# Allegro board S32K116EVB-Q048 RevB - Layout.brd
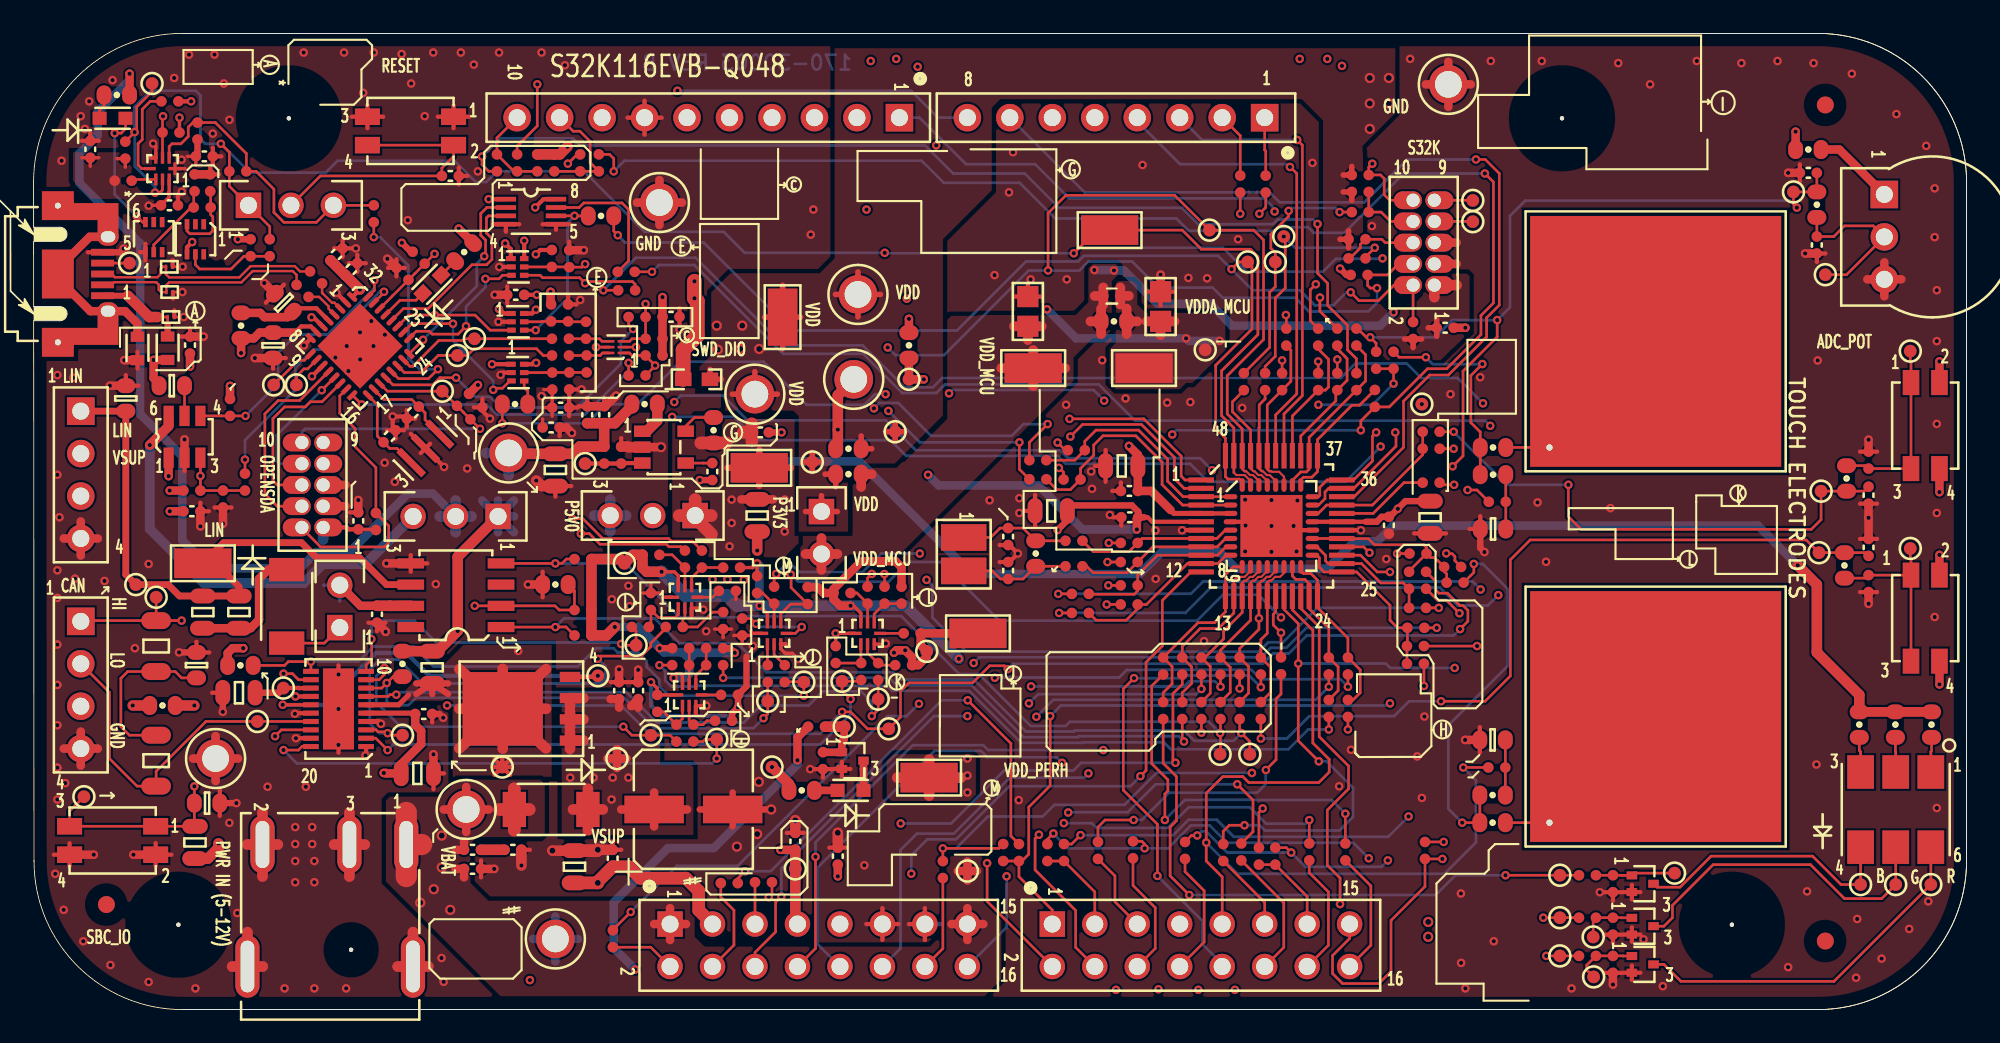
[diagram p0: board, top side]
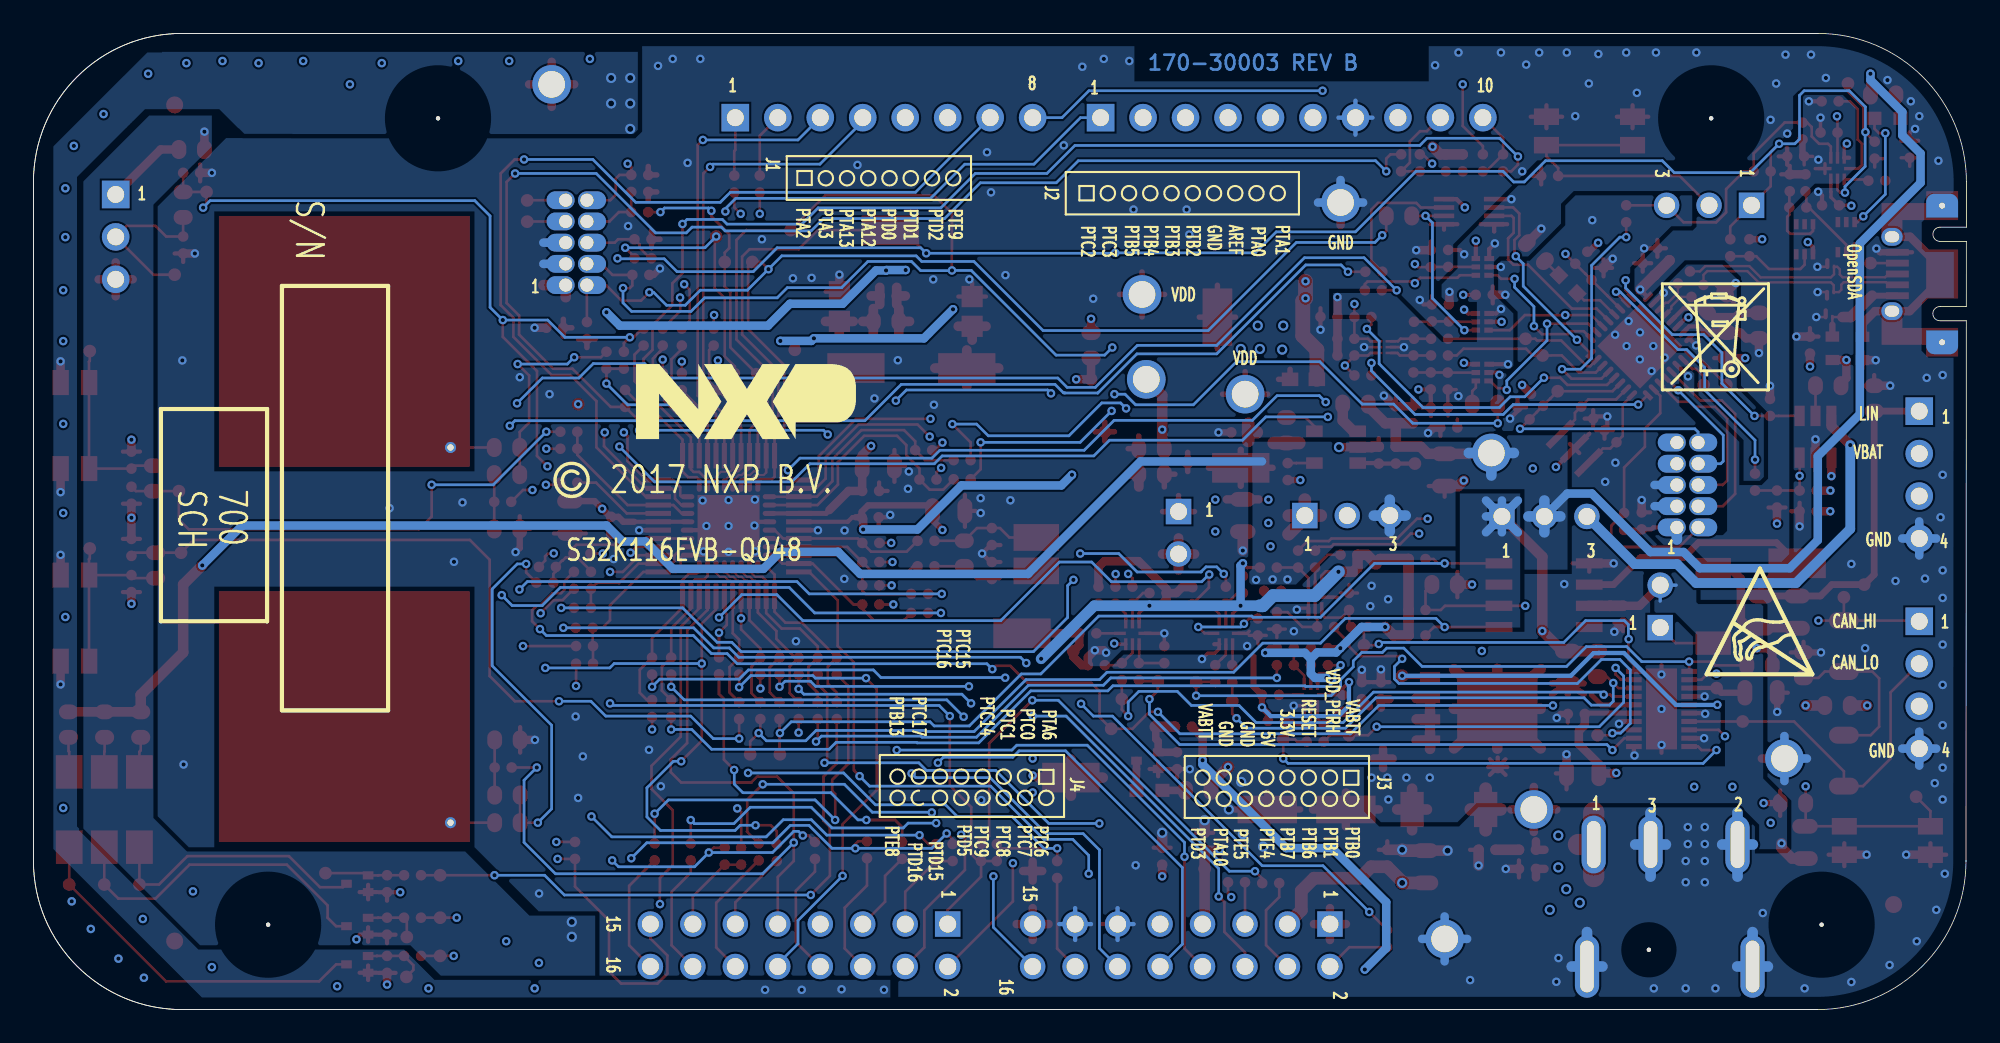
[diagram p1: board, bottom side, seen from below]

Outline 115.6 x 58.42 mm; copper layers: TOP, L2_GND_1, L3_INT_1, L4_INT_2, L5_GND_2, BOTTOM. Coordinates in mm from the lower left corner of the outline.
Outline path: 8.89,58.42 arc(2.6,55.82) 0,49.53 0,46.82 1.58,46.82 arc(2,46.4) 1.58,45.97 0,45.97 0,42.07 1.58,42.07 arc(2,41.65) 1.58,41.22 0,41.22 0.03,8.89 ; 8.89,58.42 106.71,58.42 ; 8.89,58.42 106.71,58.42 ; 0.03,8.89 0.03,8.89 ; 0.03,8.89 0.03,8.89 ; 0.03,8.89 arc(2.63,2.6) 8.92,0 ; 106.71,58.42 arc(112.99,55.82) 115.6,49.53 ; 106.71,58.42 arc(112.99,55.82) 115.6,49.53 ; 8.92,0 106.71,0 ; 8.92,0 106.71,0 ; 106.71,0 arc(112.99,2.6) 115.6,8.89 ; 106.71,0 arc(112.99,2.6) 115.6,8.89 ; 115.6,49.53 115.6,8.89 ; 115.6,49.53 115.6,8.89

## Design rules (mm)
net group CLOCK: nets SDA_EXTAL SDA_XTAL
net group SDA_USB_CONN_D: nets SDA_USB_DN SDA_USB_DP
net group USB_CONN_D: nets SDA_USB_CONN_DN SDA_USB_CONN_DP
net group POW: nets MIC2005_CSLEW POWER_EN SDA_RST SDA_USB_P5V_SENSE VTRG_EN
net group POWER: nets AREF LIN N20408163 N20498073 N20519466 N20529258 N20532266 N20759089 N20797138 N20798434 N20799004 N20829527 N20881340 N207179701 P5V0_SDA_USB_CONN_VBUS P5V_SDA_PSW SDA_USBSHIELD SDA_VOUT33 VDD_PERH VDDA_MCU
nets with their own width: min track width 0.254; nets GND

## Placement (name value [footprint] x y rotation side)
C1  1000pF  [CC0402_25]  24.92 49.89 0 top
C2  4.7uF  [CC0402_25]  3.39 51.49 90 top
C3  4.7uF  [CC0402_25]  10.21 51.06 0 top
C4  0.1UF  [CC0402_25]  8.13 48.13 0 top
C5  0.1UF  [CC0402_25]  106.64 45.76 270 top
C6  1.0UF  [CC0402_25]  18.12 45.2 45 top
C7  0.1UF  [CC0402_25]  19 44.31 45 top
C8  4.7uF  [CC0402_25]  28.83 42.77 180 top
C9  2.2UF  [CC0603_OV]  14.97 42.31 135 top
C10  0.1UF  [CC0402_25]  38.12 41.46 0 top
C11  10uF  [CC0402_25]  9.35 39.77 90 top
C12  10uF  [CC0603_OV]  14.32 39.75 270 top
C15  18PF  [CC0603_OV]  8.26 37.34 0 top
C16  0.1UF  [CC0402_25]  109.73 30.78 270 top
C17  220PF  [CC0603_OV]  5.51 36.58 90 top
C18  4.7uF  [CC0402_25]  30.95 34.84 0 top
C19  0.1UF  [CC0402_25]  31.52 36.03 0 top
C20  22PF  [CC0402_25]  22.68 35.73 225 top
C21  10.0uF  [CC0805_OV]  31.2 32.3 270 top
C22  0.1uF  [CC0402_25]  34.12 35.6 90 top
C23  22PF  [CC0402_25]  21.29 34.31 45 top
C24  10.0uF  [CC0805_OV]  43.27 29.57 270 top
C25  0.1UF  [CC0402_25]  9.47 29.82 0 top
C26  0.1UF  [CC0402_25]  19.42 29.25 90 top
C27  10.0uF  [CC0805_OV]  22.95 14.14 0 top
C28  0.1UF  [CC0402_25]  109.74 27.66 90 top
C40  4700 PF  [CC0603_OV]  9.74 20.61 90 top
C47  0.1uF  [CC0402_25]  35.01 19.09 90 top
C59  0.01UF  [CC0402_25]  40.59 32.2 270 top
C126  12PF  [CC0402_25]  58.28 28.31 270 top
C127  12PF  [CC0402_25]  58.28 26.28 90 top
C128  47uF  [CCE6P8X6P8]  39.46 11.98 0 top
C129  0.1uF  [CC0402_25]  81.05 28.98 270 top
C140  0.1uF  [CC0402_25]  65.53 31.04 180 top
C143  10UF  [CC0805_OV]  83.51 29.46 270 top
C144  10UF  [CC0805_OV]  65.07 32.54 180 top
C533  10pF  [CC0603_OV]  87.28 28.76 180 top
C535  10pF  [CC0603_OV]  87.25 16.14 180 top
C536  10.0uF  [CC0805_OV]  12.28 18.96 180 top
C542  10UF  [CC0805_OV]  60.86 29.84 180 top
C543  0.1uF  [CC0402_25]  65.56 29.46 180 top
C544  0.1uF  [CC0402_25]  26.25 9.56 0 top
C545  0.1uF  [CC0402_25]  28.66 9.56 0 top
C546  0.1uF  [CC0402_25]  36.16 19.09 90 top
C547  0.1uF  [CC0402_25]  23.33 17.69 0 top
C548  0.1uF  [CC0402_25]  43.46 34.54 0 top
C549  0.1UF  [CC0402_25]  106.13 50.08 180 top
C550  0.1uF  [CC0402_25]  33.11 35.6 90 top
C551  4700 PF  [CC0603_OV]  10.38 12.36 0 top
C552  0.1uF  [CC0402_25]  20.54 23.66 270 top
C553  0.1uF  [CC0402_25]  84.42 40.81 0 top
C554  10.0uF  [CC0805_OV]  32.35 8.55 90 top
C555  0.1uF  [CC0402_25]  26.25 8.42 0 top
C556  0.1uF  [CC0402_25]  34.63 9.06 90 top
C557  0.1uF  [CC0402_25]  45.55 10.07 90 top
C558  0.1uF  [CC0402_25]  48.09 9.18 90 top
D1  RED  [LED_0603]  4.72 53.34 0 top
D2  LED GREEN  [LED_0603]  23.82 43.41 225 top
D3  GREEN  [LED_0603]  48.86 13.12 0 top
D6  PMEG3050EP  [SOD-128]  15.14 24.13 90 top
D9  PMEG3050EP  [SOD-128]  30.95 11.98 0 top
D11  LED RED/GRN/BL  [LED6_5X6MM]  111.36 11.97 270 top
D17  PESD5V0R1BSF  [DSN0603-2]  8.22 41.45 180 top
D18  PESD5V0R1BSF  [DSN0603-2]  8.12 44.46 180 top
D19  PESD5V0R1BSF  [DSN0603-2]  8.14 42.94 180 top
D59  VC080505C150RP  [0805]  59.46 41.78 90 top
D60  VC080505C150RP  [0805]  67.4 42.08 90 top
GND1  5006  [TP_TH_063]  31.2 4.23 0 top
GND2  5006  [TP_TH_063]  84.61 55.37 0 top
GND3  5006  [TP_TH_063]  10.88 15.02 0 top
GND4  5006  [TP_TH_063]  37.43 48.3 0 top
J1  SKT_1X8  [CON_SKT1X8_TH]  73.62 53.38 270 top
J2  SKT_1X10  [CON_SKT1X10_TH]  51.78 53.38 270 top
J3  SKT_2X8  [SKT2X8_TH_SSQ]  38.06 5.12 90 top
J4  SKT_2X8  [SKT2X8_TH_SSQ]  60.92 5.12 90 top
J7  USB_MICRO_AB  [CON_MICROAB_10F_25_SM_RA]  1.55 44.02 0 top
J10  HDR TH 1X3  [HDR103]  39.57 29.57 270 top
J11  HDR 1X4 RA  [CON_HDR_4M_100_TH_RA]  2.82 35.81 270 top
J12  HDR 2X5  [CON_2RH_10_50]  17.32 28.86 90 top
J13  HDR 1X4 RA  [CON_HDR_4M_100_TH_RA]  2.82 23.24 270 top
J14  HDR 2X5  [CON_2RH_10_50]  83.77 43.36 90 top
J15  HDR 1X2  [HDR102]  47.12 29.81 0 top
J16  CON PWR 3  [CON3_PWR_JACK_TH_PJ051A]  22.29 9.88 90 top
J104  HDR TH 1X3  [HDR103]  12.85 48.13 90 top
J107  HDR TH 1X3  [HDR103]  27.78 29.51 270 top
J108  HDR 1X2  [HDR102]  18.31 22.86 180 top
L1  330 OHM  [IND_1608]  8.02 39.58 270 top
L2  330 OHM  [IND_1608]  6.21 39.57 270 top
L512  30 OHM  [IND_0402]  64.48 42.71 180 top
NOREF  -  []  35.9 38.07 90 top
NOREF#2  -  []  1.58 42.07 0 top
NOREF#3  -  []  20.03 15.44 0 top
NOREF#4  -  []  38.48 18.21 0 top
NOREF#5  -  []  43.56 21.89 0 top
NOREF#6  -  []  114.92 24.63 0 top
NOREF#7  -  [unnamed#2]  8.66 5.08 0 top
NOREF#8  -  []  0 46.4 0 top
NOREF#9  -  []  -35.57 -162.37 0 top
NOREF#10  -  []  39.15 24.06 90 top
NOREF#11  -  []  71.53 26.44 90 top
NOREF#12  -  [unnamed#2]  15.26 53.34 0 top
NOREF#13  -  []  -408 -337.34 0 top
NOREF#14  -  []  2.33 11.92 0 top
NOREF#15  -  []  119.72 32.55 90 top
NOREF#16  -  []  108.31 14.52 0 top
NOREF#17  -  []  0.03 8.89 0 top
NOREF#18  -  []  -381.97 187.81 0 top
NOREF#19  -  []  34.85 38.07 0 top
NOREF#20  -  []  95.76 36.47 270 top
NOREF#21  -  []  69.82 26.19 90 top
NOREF#22  -  []  2.15 10.97 0 top
NOREF#23  -  []  7.92 44.46 0 top
NOREF#24  -  []  113.41 14.52 90 top
NOREF#25  -  []  137.96 58.44 0 top
NOREF#26  -  []  34.42 39.65 90 top
NOREF#27  -  []  9.05 44.62 90 top
NOREF#28  -  []  119.72 21.03 90 top
NOREF#29  -  []  49.47 21.87 0 top
NOREF#30  -  []  70.33 40.97 90 top
NOREF#31  -  []  50.07 21.9 90 top
NOREF#32  -  []  50.63 37.72 0 top
NOREF#33  -  []  67.4 41.19 90 top
NOREF#34  -  []  62.39 40.68 90 top
NOREF#35  -  []  76.48 27.19 90 top
NOREF#36  -  []  8.66 5.08 0 top
NOREF#37  -  []  72.28 31.39 0 top
NOREF#38  -  []  7.51 3.98 0 top
NOREF#39  -  []  91.4 53.34 0 top
NOREF#40  -  []  32.79 4.23 0 top
NOREF#41  -  []  72.28 26.49 0 top
NOREF#42  -  []  8.02 41.45 0 top
NOREF#43  -  []  -16.59 -34.16 0 top
NOREF#44  -  []  53.34 39.01 0 top
NOREF#45  -  []  15.14 21.93 90 top
NOREF#46  -  []  44.68 21.87 90 top
NOREF#47  -  []  112.27 37.53 0 top
NOREF#48  -  [unnamed#2]  4.36 6.29 0 top
NOREF#49  -  []  0 41.65 0 top
NOREF#50  -  []  109.26 9.72 90 top
NOREF#51  -  []  8.53 41.61 0 top
NOREF#52  -  []  71.58 30.69 0 top
NOREF#53  -  []  69.82 31.7 0 top
NOREF#54  -  []  25.63 15.44 90 top
NOREF#55  -  []  91.4 53.34 0 top
NOREF#56  -  []  113.77 54.93 0 top
NOREF#57  -  []  28.75 11.98 0 top
NOREF#58  -  []  19.88 15.74 90 top
NOREF#59  -  []  7.13 8.32 90 top
NOREF#60  -  []  71.53 26.44 90 top
NOREF#61  -  []  7.71 50.98 0 top
NOREF#62  -  [unnamed#2]  91.4 53.34 0 top
NOREF#63  -  []  112.27 32.38 90 top
NOREF#64  -  []  16.58 20.24 0 top
NOREF#65  -  []  19.96 53.43 0 top
NOREF#66  -  []  75.78 26.49 90 top
NOREF#67  -  []  8.89 58.42 0 top
NOREF#68  -  []  19.88 15.74 90 top
NOREF#69  -  []  39.35 24.03 90 top
NOREF#70  -  [unnamed#2]  101.56 5.08 0 top
NOREF#71  -  []  112.27 26 0 top
NOREF#72  -  []  39.01 48.3 0 top
NOREF#73  -  []  34.42 40 0 top
NOREF#74  -  [unnamed#2]  107.15 4.1 0 top
NOREF#75  -  []  70.52 25.44 0 top
NOREF#76  -  []  113.05 29.39 0 top
NOREF#77  -  []  28.95 13.33 0 top
NOREF#78  -  []  20.14 54.38 0 top
NOREF#79  -  []  44.72 36.83 0 top
NOREF#80  -  []  7.94 42.94 0 top
NOREF#81  -  []  8.43 44.62 0 top
NOREF#82  -  []  27.46 11.98 0 top
NOREF#83  -  []  16.49 22.13 0 top
NOREF#84  -  []  39.4 18.21 90 top
NOREF#85  -  []  76.78 24.74 90 top
NOREF#86  -  []  7.3 9.27 90 top
NOREF#87  -  []  71.53 26.44 0 top
NOREF#88  -  []  8.45 43.1 0 top
NOREF#89  -  []  43.88 21.87 0 top
NOREF#90  -  []  38.23 24.05 0 top
NOREF#91  -  []  38.8 18.18 0 top
NOREF#92  -  []  12.47 15.02 0 top
NOREF#93  -  []  7.91 49.71 90 top
NOREF#94  -  []  19.19 18.13 90 top
NOREF#95  -  []  76.53 31.44 0 top
NOREF#96  -  []  71.53 26.44 0 top
NOREF#97  -  []  72.28 26.49 0 top
NOREF#98  -  [unnamed#2]  107.15 54.14 0 top
NOREF#99  -  []  101.56 5.08 0 top
NOREF#100  -  []  28.95 10.63 90 top
NOREF#101  -  []  71.28 33.15 0 top
NOREF#102  -  []  59.46 40.89 90 top
NOREF#103  -  []  76.48 27.19 90 top
NOREF#104  -  []  1.91 46.66 0 top
NOREF#105  -  []  78.85 41.27 0 top
NOREF#106  -  []  15.26 53.34 0 top
NOREF#107  -  []  119.21 -11.77 0 top
NOREF#108  -  []  44.48 21.9 90 top
NOREF#109  -  []  24.94 50.78 90 top
NOREF#110  -  []  86.19 55.37 0 top
NOREF#111  -  []  115.6 8.89 0 top
NOREF#112  -  []  71.58 30.69 0 top
NOREF#113  -  []  68.12 40.97 0 top
NOREF#114  -  []  38.55 24.03 0 top
NOREF#115  -  []  71.58 27.19 90 top
NOREF#116  -  []  111.36 9.72 0 top
NOREF#117  -  []  77.53 25.44 90 top
NOREF#118  -  []  75.78 26.49 90 top
NOREF#119  -  []  8.92 0 0 top
NOREF#120  -  []  39.6 18.18 90 top
NOREF#121  -  []  49.15 21.89 0 top
NOREF#122  -  []  9.15 41.61 90 top
NOREF#123  -  []  8.66 5.08 0 top
NOREF#124  -  []  50.89 42.8 0 top
NOREF#125  -  []  25.12 51.73 90 top
NOREF#126  -  []  50.27 21.87 90 top
NOREF#127  -  []  112.27 20.85 90 top
NOREF#128  -  []  72.28 31.39 0 top
NOREF#129  -  []  -67.9 -131.95 0 top
NOREF#130  -  []  114.92 36.15 0 top
NOREF#131  -  []  8.43 50.96 0 top
NOREF#132  -  []  6.96 50.33 90 top
NOREF#133  -  []  1.58 41.22 0 top
NOREF#134  -  []  60.18 40.68 0 top
NOREF#135  -  []  30 33.31 0 top
NOREF#136  -  []  9.07 43.1 90 top
NOREF#137  -  []  15.52 20.07 180 bottom
NOREF#138  -  []  107.97 48.64 270 bottom
NOREF#139  -  []  19.07 37.72 180 bottom
NOREF#140  -  []  79.55 34.14 180 bottom
NOREF#141  -  []  83.41 31.67 180 bottom
NOREF#142  -  []  100.73 43.31 270 bottom
NOREF#143  -  []  114.07 38.1 270 bottom
NOREF#144  -  []  91.82 42.06 180 bottom
Q1  PHPT61003PY  [LFPAK5_1P27_5X4]  29.1 18 90 top
Q6  MMBT3904TT1G  [SC_75]  96.23 2.71 270 top
Q7  MMBT3904TT1G  [SC_75]  96.23 4.99 270 top
Q8  MMBT3904TT1G  [SC_75]  96.23 7.53 270 top
Q9  MMBT3904TT1G  [SC_75]  48.98 14.9 270 top
Q10  BC847BVN  [SOT-563_6P_0P5_SMT]  9.68 46.1 270 top
Q11  BC847BVN  [SOT-563_6P_0P5_SMT]  7.19 46.23 90 top
R1  4.7K  [RC0402_25]  8.15 54.36 0 top
R3  10.0K  [RC0402_25]  9.8 52.58 90 top
R4  180K  [RC0402_25]  5.48 51.43 90 top
R5  0  [RC0402_25]  12.22 50.16 180 top
R12  220  [RC0603_OV]  25.75 45.33 225 top
R13  5K  [POT3_3352T]  110.68 48.78 270 top
R14  4.7K  [RC0402_25]  23.03 45 315 top
R15  4.7K  [RC0402_25]  30.99 44.95 270 top
R16  10.0K  [RC0402_25]  32.03 44.94 90 top
R18  0  [RC0402_25]  35.44 44.16 0 top
R20  10.0K  [RC0402_25]  22.06 44.03 135 top
R21  33  [RC0402_25]  16.89 43.82 315 top
R24  0  [RC0402_25]  35.47 43.05 180 top
R25  33  [RC0402_25]  16.09 43.01 315 top
R30  4.7K  [RC0402_25]  30.95 41.69 270 top
R31  10.0K  [RC0402_25]  31.97 41.69 90 top
R32  0  [RC0402_25]  36.09 41.45 180 top
R35  0  [RC0402_25]  33.04 40.65 90 top
R38  0  [RC0402_25]  31.51 40.15 180 top
R39  10.0K  [RC0402_25]  37.11 40.15 0 top
R41  0  [RC0402_25]  31.51 39.15 180 top
R42  10.0K  [RC0402_25]  37.11 39.15 180 top
R44  10.0K  [RC0402_25]  109.74 32.88 90 top
R47  0  [RC0402_25]  33.07 38.64 270 top
R49  0  [RC0402_25]  36.09 37.95 180 top
R51  10.0K  [RC0402_25]  32.03 37.62 270 top
R52  4.7K  [RC0402_25]  31.02 37.61 90 top
R56  680  [RC0603_OV]  45.94 13.12 0 top
R57  4.7K  [RC0402_25]  25.68 36.49 225 top
R60  10.0K  [RC0402_25]  11.75 36.04 270 top
R62  10.0K  [RC0402_25]  26.48 35.68 45 top
R68  15K  [RC0402_25]  11.33 30.56 270 top
R69  1.0K  [RC0402_25]  12.64 31.57 270 top
R70  10.0K  [RC0402_25]  9.47 31.06 0 top
R74  10.0K  [RC0402_25]  109.74 25.49 270 top
R77  10.0K  [RC0402_25]  20.47 29.21 90 top
R80  2K  [RC0805_OV]  10.12 23.79 270 top
R84  0  [RC0402_25]  62.22 26.53 0 top
R88  0  [RC0402_25]  62.22 28.05 0 top
R91  1.0M  [RC0603_OV]  59.93 27.29 270 top
R92  60.4  [RC1206_OV]  7.33 21.76 270 top
R95  680  [RC0603_OV]  109.18 17.06 90 top
R96  680  [RC0603_OV]  111.34 17.06 90 top
R97  680  [RC0603_OV]  113.5 17.06 90 top
R98  60.4  [RC1206_OV]  7.33 14.9 270 top
R117  0  [RC0603_OV]  48.73 32.04 0 top
R119  0  [RC0402_25]  79.14 44.96 0 top
R120  0  [RC0402_25]  79.34 47.73 180 top
R121  10K  [RC0402_25]  82.5 40.64 90 top
R169  0  [RC0402_25]  34.12 33.19 270 top
R170  0  [RC0402_25]  35.14 33.19 270 top
R171  2K  [RC0805_OV]  12.28 23.79 270 top
R172  0  [RC0603_OV]  87.28 33.64 180 top
R300  0  [RC0603_OV]  64.6 41.19 0 top
R525  4.7K  [RC0603_OV]  87.28 32.01 180 top
R527  0  [RC0603_OV]  87.25 11.19 180 top
R528  4.7K  [RC0603_OV]  87.25 12.84 180 top
R530  10.0K  [RC0402_25]  32.85 23.91 180 top
R535  2.2  [RC0805_OV]  23.84 20.49 270 top
R536  4.7K  [RC0603_OV]  12.37 20.6 0 top
R537  10k  [RC0805_OV]  9.65 10 90 top
R538  10.0K  [RC0402_25]  32.85 22.39 180 top
R562  4.7K  [RC0402_25]  42.38 22.9 90 top
R569  0  [RC0603_OV]  52.35 39.75 90 top
R570  10.0K  [RC0402_25]  32.85 26.96 180 top
R571  4.7K  [RC0402_25]  52.54 22.52 180 top
R572  4.7K  [RC0402_25]  41.49 25.06 180 top
R573  10K  [RC0402_25]  79.14 46.1 0 top
R574  10K  [RC0402_25]  79.34 49.95 0 top
R575  10K  [RC0402_25]  79.27 43.97 180 top
R576  4.7K  [RC0402_25]  41.62 18.83 180 top
R577  0  [RC0402_25]  43.9 20.1 90 top
R578  0  [RC0402_25]  44.92 20.1 90 top
R579  0  [RC0402_25]  49.49 20.23 90 top
R580  0  [RC0402_25]  50.51 20.23 90 top
R581  0  [RC0402_25]  36.28 22.9 0 top
R582  0  [RC0402_25]  38.32 22.9 0 top
R583  0  [RC0402_25]  38.44 16.55 90 top
R584  0  [RC0402_25]  39.46 16.55 90 top
R585  0  [RC0402_25]  44.28 24.8 90 top
R587  0  [RC0402_25]  49.87 24.8 90 top
R588  0  [RC0402_25]  50.89 24.8 90 top
R589  0  [RC0402_25]  38.95 26.96 90 top
R590  0  [RC0402_25]  39.97 26.96 90 top
R591  0  [RC0402_25]  38.7 20.61 180 top
R592  0  [RC0402_25]  40.73 20.61 0 top
R593  0  [RC0603_OV]  48.73 33.57 180 top
R594  4.7K  [RC0603_OV]  22.06 20.69 270 top
R595  1K  [RC0603_OV]  108.29 26.58 90 top
R596  1K  [RC0603_OV]  108.42 31.79 270 top
R597  1K  [RC0603_OV]  106.64 48.17 90 top
R598  10K  [RC0402_25]  92.93 3.21 0 top
R599  33K  [RC0402_25]  94.45 2.71 270 top
R600  33K  [RC0402_25]  94.45 4.99 270 top
R601  10K  [RC0402_25]  92.93 5.5 0 top
R602  33K  [RC0402_25]  94.45 7.53 270 top
R603  10K  [RC0402_25]  92.93 8.04 0 top
R604  10K  [RC0402_25]  46.82 16.93 0 top
R605  33K  [RC0402_25]  47.21 14.9 270 top
R606  0  [RC0603_OV]  7.71 18.2 0 top
R607  10.0K  [RC0402_25]  8.22 52.49 180 top
R608  10.0K  [RC0402_25]  5.36 49.61 0 top
R609  10.0K  [RC0402_25]  46.29 24.77 270 top
R610  10.0K  [RC0402_25]  48.35 24.93 0 top
R611  10.0K  [RC0402_25]  51.9 24.8 270 top
R612  10.0K  [RC0402_25]  41.74 26.45 180 top
R613  10.0K  [RC0402_25]  36.92 27.22 0 top
R614  10.0K  [RC0402_25]  40.73 21.63 180 top
R615  10.0K  [RC0402_25]  38.7 21.63 0 top
R616  10.0K  [RC0402_25]  43.27 25.44 270 top
R617  10.0K  [RC0402_25]  47.97 21.25 270 top
R618  10.0K  [RC0402_25]  52.03 20.61 180 top
R619  10.0K  [RC0402_25]  36.92 24.42 270 top
R620  10.0K  [RC0402_25]  41.24 23.28 90 top
R621  10.0K  [RC0402_25]  37.3 18.33 270 top
R622  10.0K  [RC0402_25]  41.26 17.28 180 top
R623  10K  [RC0402_25]  79.34 48.93 0 top
R624  0  [RC0603_OV]  36.54 36.23 0 top
R625  0  [RC0603_OV]  33.93 47.5 180 top
R626  0  [RC0603_OV]  28.79 36.23 0 top
R627  0  [RC0603_OV]  12.41 40.93 270 top
R632  0  [RC0402_25]  72.38 37.58 270 top
R635  0  [RC0402_25]  68.69 17.89 90 top
R636  0  [RC0402_25]  69.84 17.89 90 top
R637  0  [RC0402_25]  77.46 18.02 90 top
R638  0  [RC0402_25]  78.6 18.02 90 top
R639  0  [RC0402_25]  68.69 20.56 90 top
R640  0  [RC0402_25]  69.84 20.56 90 top
R641  0  [RC0402_25]  77.46 20.56 90 top
R642  0  [RC0402_25]  78.6 20.56 90 top
R643  0  [RC0402_25]  65.52 27.93 0 top
R644  0  [RC0402_25]  65.52 26.78 0 top
R645  0  [RC0402_25]  73.65 37.58 270 top
R649  0  [RC0402_25]  60.06 31.74 180 top
R650  0  [RC0402_25]  60.06 32.88 180 top
R651  0  [RC0402_25]  62.1 31.72 180 top
R652  0  [RC0402_25]  62.36 33.48 180 top
R653  0  [RC0402_25]  62.6 24.88 180 top
R654  0  [RC0402_25]  62.6 23.74 180 top
R655  0  [RC0402_25]  67.55 17.89 270 top
R656  0  [RC0402_25]  65.52 25.39 180 top
R657  0  [RC0402_25]  65.52 24.24 180 top
R658  0  [RC0402_25]  67.55 20.56 270 top
R659  0  [RC0402_25]  83.58 34.58 0 top
R660  0  [RC0402_25]  73.39 17.89 270 top
R661  4.7K  [RC0603_OV]  31.2 25.44 180 top
R662  0  [RC0402_25]  82.77 24.04 180 top
R663  0  [RC0402_25]  82.66 22.85 180 top
R664  0  [RC0402_25]  72.12 17.89 90 top
R665  0  [RC0402_25]  70.98 17.89 90 top
R666  0  [RC0402_25]  82.77 25.18 180 top
R667  0  [RC0402_25]  82.64 21.76 180 top
R668  0  [RC0402_25]  74.92 40.25 270 top
R669  0  [RC0402_25]  74.66 37.58 270 top
R670  0  [RC0402_25]  79.11 40.25 270 top
R671  0  [RC0402_25]  82.79 27.29 0 top
R672  0  [RC0402_25]  82.77 26.2 180 top
R673  0  [RC0402_25]  79.11 37.58 270 top
R674  0  [RC0603_OV]  106.13 51.47 0 top
R675  0  [RC0402_25]  73.68 49.4 90 top
R676  0  [RC0402_25]  72.16 49.4 90 top
R677  0  [RC0402_25]  70.98 20.56 90 top
R678  0  [RC0402_25]  72.12 20.56 90 top
R679  0  [RC0402_25]  76.82 40.25 90 top
R680  0  [RC0402_25]  77.97 40.25 90 top
R681  0  [RC0402_25]  83.58 31.53 0 top
R683  0  [RC0402_25]  76.82 37.58 90 top
R684  0  [RC0402_25]  77.97 37.58 90 top
R685  0  [RC0402_25]  74.26 9.18 270 top
R686  0  [RC0402_25]  71.14 9.4 270 top
R687  0  [RC0402_25]  63.65 9.53 270 top
R693  0  [RC0402_25]  72.22 9.44 270 top
R694  0  [RC0402_25]  76.29 9.44 270 top
R695  0  [RC0402_25]  78.45 9.44 270 top
R696  0  [RC0402_25]  83.58 33.57 0 top
R697  0  [RC0402_25]  73.39 20.56 270 top
R701  0  [RC0402_25]  20.34 47.62 90 top
R702  0  [RC0402_25]  65.75 9.56 270 top
R703  0  [RC0402_25]  68.86 9.53 270 top
R711  0  [RC0402_25]  80.29 38.86 90 top
R712  10.0K  [RC0402_25]  30.12 50.67 270 top
R713  10.0K  [RC0402_25]  31.14 50.67 270 top
R715  0  [RC0402_25]  43.65 7.62 180 top
R716  0  [RC0402_25]  32.69 50.67 270 top
R717  0  [RC0402_25]  28.92 50.67 270 top
R718  0  [RC0402_25]  27.71 50.67 90 top
R719  0  [RC0402_25]  33.81 50.67 270 top
R727  0  [RC0402_25]  82.64 20.7 180 top
R729  560 OHM  [RC0603_OV]  4.98 54.74 0 top
R730  10.0K  [RC0402_25]  10.08 48.01 180 top
R731  100K  [RC0402_25]  10.56 49.48 90 top
R732  18K  [RC0402_25]  14.12 45.59 270 top
R733  4.7K  [RC0402_25]  12.98 45.59 270 top
R734  180K  [RC0402_25]  9.63 49.48 90 top
R737  0  [RC0603_OV]  40.66 34.67 270 top
R739  0  [RC0402_25]  74.6 20.57 270 top
R740  0  [RC0402_25]  81.33 38.86 90 top
R741  0  [RC0402_25]  80.21 36.58 90 top
R742  0  [RC0402_25]  61.62 9.4 270 top
R743  0  [RC0402_25]  73.28 9.18 270 top
R744  0  [RC0402_25]  87.53 30.39 0 top
R745  0  [RC0402_25]  60.63 9.4 270 top
R746  0  [RC0402_25]  87.51 14.49 0 top
R747  0  [RC0402_25]  85.01 25.55 180 top
R748  0  [RC0402_25]  83.21 9.53 270 top
R749  0  [RC0402_25]  58.93 9.4 270 top
R750  0  [RC0402_25]  84.86 26.49 180 top
R751  0  [RC0402_25]  57.99 9.4 270 top
R752  0  [RC0402_25]  54.38 8.38 270 top
R753  0  [RC0402_25]  41.6 7.57 180 top
R754  0  [RC0402_25]  34.64 4.24 270 top
SH1  0  [SH0603]  39.65 37.72 0 top
SW2  EVQ-P2402W  [SW4_SPST_4P8X3P6_2P5]  113.12 34.95 90 top
SW3  EVQ-P2402W  [SW4_SPST_4P8X3P6_2P5]  113.12 23.43 90 top
SW5  EVQ-P2402W  [SW4_SPST_4P8X3P6_2P5]  22.54 52.58 0 top
SW7  Electrode  [ELECTRODE_SQ_15MM]  97 39.99 90 top
SW8  Electrode  [ELECTRODE_SQ_15MM]  97 17.54 90 top
SW9  EVQ-P2402W  [SW4_SPST_4P8X3P6_2P5]  4.73 10.12 0 top
TP4  TEST_POINT  [TP_TH_063]  49.3 42.8 270 top
TP5  -  [TPAD_030]  107.15 43.98 270 top
TP6  -  [TPAD_030]  5.74 44.67 90 top
TP7  -  [TPAD_030]  26.37 40.15 315 top
TP8  -  [TPAD_030]  25.35 39.15 315 top
TP9  TEST_POINT  [TP_TH_063]  43.13 36.83 270 top
TP10  -  [TPAD_030]  14.36 37.39 90 top
TP11  -  [TPAD_030]  15.72 37.39 90 top
TP12  -  [TPAD_030]  24.44 37.01 90 top
TP18  -  [TPAD_030]  6.11 25.43 90 top
TP28  -  [TPAD_030]  109.26 7.48 270 top
TP29  -  [TPAD_030]  111.36 7.48 0 top
TP30  -  [TPAD_030]  113.46 7.48 90 top
TP503  -  [TPAD_030]  13.38 17.24 0 top
TP504  -  [TPAD_030]  7.33 24.68 0 top
TP505  -  [TPAD_030]  46.06 19.6 0 top
TP506  -  [TPAD_030]  43.9 18.45 0 top
TP507  -  [TPAD_030]  55.84 8.29 0 top
TP508  -  [TPAD_030]  34.89 15.02 0 top
TP509  -  [TPAD_030]  44.16 14.52 0 top
TP510  -  [TPAD_030]  45.55 8.42 0 top
TP511  -  [TPAD_030]  51.52 34.58 0 top
TP512  -  [TPAD_030]  50.51 18.58 0 top
TP513  -  [TPAD_030]  48.35 19.65 0 top
TP514  -  [TPAD_030]  36.03 21.81 0 top
TP515  -  [TPAD_030]  22.06 16.42 0 top
TP516  -  [TPAD_030]  36.92 16.42 0 top
TP517  -  [TPAD_030]  40.86 16.17 0 top
TP518  -  [TPAD_030]  3.01 12.74 0 top
TP519  -  [TPAD_030]  72.73 15.28 0 top
TP520  -  [TPAD_030]  70.95 15.28 0 top
TP521  -  [TPAD_030]  51.14 16.8 0 top
TP522  TEST_POINT  [TP_TH_063]  25.87 11.98 0 top
TP523  -  [TPAD_030]  28.03 14.52 0 top
TP524  -  [TPAD_030]  33.74 19.98 0 top
TP525  -  [TPAD_030]  53.41 21.44 0 top
TP526  TEST_POINT  [TP_TH_063]  49.05 37.72 0 top
TP527  TEST_POINT  [TP_TH_063]  28.41 33.31 0 top
TP528  -  [TPAD_030]  105.24 48.93 0 top
TP529  -  [TPAD_030]  106.77 27.34 0 top
TP530  -  [TPAD_030]  106.9 31.03 0 top
TP531  -  [TPAD_030]  112.23 27.6 0 top
TP532  -  [TPAD_030]  112.23 39.41 0 top
TP533  -  [TPAD_030]  83.02 36.23 0 top
TP534  -  [TPAD_030]  70.07 39.48 0 top
TP535  -  [TPAD_030]  72.61 44.74 0 top
TP536  -  [TPAD_030]  70.32 46.65 0 top
TP537  -  [TPAD_030]  74.76 46.27 0 top
TP538  -  [TPAD_030]  74.26 44.74 0 top
TP539  -  [TPAD_030]  7.09 55.42 0 top
TP540  -  [TPAD_030]  32.98 32.68 0 top
TP541  -  [TPAD_030]  35.33 26.71 0 top
TP542  -  [TPAD_030]  86.07 47.16 0 top
TP543  -  [TPAD_030]  86.07 48.43 0 top
TP544  -  [TPAD_030]  14.94 19.24 0 top
TP545  -  [TPAD_030]  52.35 37.72 0 top
TPAD93  -  [TPAD_030]  93.29 1.96 0 top
TPAD94  -  [TPAD_030]  91.27 3.21 0 top
TPAD95  -  [TPAD_030]  91.27 5.5 0 top
TPAD96  -  [TPAD_030]  93.27 4.34 0 top
TPAD97  -  [TPAD_030]  91.27 8.04 0 top
TPAD98  -  [TPAD_030]  98.13 8.17 0 top
TPAD99  -  [TPAD_030]  46.57 32.77 0 top
TPAD100  -  [TPAD_030]  48.48 16.93 0 top
TS1  TESTLOOP  [TESTPOINT_135_070MIL]  44.79 41.44 90 top
TS2  TESTLOOP  [TESTPOINT_135_070MIL]  59.78 38.39 180 top
TS3  TESTLOOP  [TESTPOINT_135_070MIL]  66.41 38.39 180 top
TS4  TESTLOOP  [TESTPOINT_135_070MIL]  10.12 26.71 0 top
TS5  TESTLOOP  [TESTPOINT_135_070MIL]  43.4 32.42 0 top
TS6  TESTLOOP  [TESTPOINT_135_070MIL]  53.56 13.88 180 top
TS7  TESTLOOP  [TESTPOINT_135_070MIL]  64.35 46.65 180 top
TS8  TESTLOOP  [TESTPOINT_135_070MIL]  56.48 22.52 0 top
U1  NTSX2102GU8H  [XQFN8_1P45X1P25MM]  7.71 50.33 180 top
U2  74LVC2T45DC  [SSOP8_DCU]  29.74 47.75 270 top
U4  74LVCH1T45  [UDFN6_1X1P5MM]  28.96 44.44 0 top
U7  74LVCH1T45  [UDFN6_1X1P5MM]  28.96 41.16 0 top
U8  MK20DX128VFM5  [QFN32_S142EP]  19.52 39.71 315 top
U9  74LVC2G14GF,132  [SOT891_6P_0P35_1P05X1P05]  34.83 39.65 180 top
U10  74LVCH1T45  [UDFN6_1X1P5MM]  28.96 38.12 0 top
U11  MIC2005-0.8YM6  [SOT23-6_A]  9.03 34.28 90 top
U15  SPX3819M5-L-3-3  [SOT23_5S]  37.7 33.66 270 top
U19  UJA1169TK/F  [SON20_0P5_3P6X5P6]  18.23 17.99 90 top
U21  TJA1027T/20  [SO8_1P27_4X5]  25.26 24.8 180 top
U26  NTSX2102GU8H  [XQFN8_1P45X1P25MM]  38.95 24.68 0 top
U32  NTSX2102GU8H  [XQFN8_1P45X1P25MM]  44.28 22.52 0 top
U33  NTSX2102GU8H  [XQFN8_1P45X1P25MM]  49.87 22.52 0 top
U34  NTSX2102GU8H  [XQFN8_1P45X1P25MM]  39.2 18.83 0 top
U36  PS32K116LFF0MLCR  [LQFP48]  74.03 28.94 0 top
U37  S32K116  [QFN32_0P5_5X5_S146EP]  74.03 28.94 0 top
Y1  8.00MHZ  [XTAL3_3P35X1P45_SM]  23.43 33.58 45 top
Y3  40MHz  [XTAL2_3P3X2P6]  55.62 27.25 270 top

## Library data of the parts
C1 C6 C9 C11 C16 C17 C20-C24 C27 C28 C40 C47 C126 C127 C129 C140 C143 C144 C536 C542-C548 C550-C558 = CAP_NP
C2-C5 C7 C8 C10 C12 C18 C19 C25 C26 C533 C535 C549 = CAP_NP: tolerance: 10%
C15 = CAP_NP: tolerance: 5%
C59 = CAP_NP: tolerance: 20%
C128 = CAP_POL
D1-D3 = LED
D6 D9 = DIODE_SCHTKY
D11 = LED_TRI_COLOR
D17-D19 = DIODE_BIDIR
D59 D60 = TRANZORB_BIDIR_AA
GND1-GND4 = TEST_POINT_3
J1 = CONN_HDR_8X1
J2 = CONN_HDR_10X1
J3 J4 = CONN_HDR_8X2
J7 = MICRO_USB_CONN_10PIN
J10 J104 J107 = CONN_HDR_3X1
J11 J13 = CONN_HDR_4X1
J12 J14 = CONN_HDR_5X2: User Part Number: 210-07961-00
J15 J108 = CONN_HDR_2X1
J16 = DC_POWER_JACK_SHD
L1 L2 = BEAD
L512 = INDUCTOR_FERRITE
Q1 = PMOS_5P
Q6-Q9 = NPN
Q10 Q11 = BJT_DUAL_PNP_NPN
R1 R14 R15 R30 R44 R52 R57 R60 R68-R70 R74 R562 R571 R572 R576 = RES: tolerance: 1%
R3 R5 R16 R18 R24 R31 R39 R42 R51 R530 R538 R570 R607-R622 R701 R712 R713 R730 = RES: tolerance: 5%
R4 R12 R20 R21 R25 R32 R35 R38 R41 R47 R49 R56 R62 R77 R80 R84 R88 R91 R92 R95-R98 R117 R119-R121 R169-R172 R300 R525 R527 R528 R535-R537 R569 R573-R575 R577-R585 R587-R606 R623-R627 R632 R635-R645 R649-R681 R683-R687 R693-R697 R702 R703 R711 R715-R719 R727 R729 R731-R734 R737 R739-R754 = RES
R13 = POT: tolerance: 20%
SH1 = RES_SHORT-2
SW2 SW3 SW5 SW9 = EDGE_MOUNT_PB_SW_2
SW7 SW8 = ELECTRODE
TP4 TP9 TP522 TP526 TP527 = TEST_POINT_0
TP5-TP8 TP10-TP12 TP18 TP28-TP30 TP503-TP521 TP523-TP525 TP528-TP545 TPAD93-TPAD100 = TestLoop
TS1-TS8 = TEST_POINT_4
U1 = NTSX2102GU8H_8P
U2 = 74LVC2T45DC_8P
U4 U7 U10 = 74LVCH1T45_6P
U8 = PK20DX128V_QFN_32P
U9 = NC7WP14
U11 = MIC2005-0.8YM6
U15 = SPX3819M5_FIX_0
U19 = UJA1169TKF_3
U21 = TJA1027T_0
U26 U32-U34 = NTSX2102GU8H_0
U36 = PS32K116_LQFP_0
U37 = S32K116_QFN_0
Y1 = XTAL_CS
Y3 = XTAL

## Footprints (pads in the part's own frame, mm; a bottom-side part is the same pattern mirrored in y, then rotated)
0805
  rect 1.27x1.27 smd: 1(-0.889,0) 2(0.889,0)
CC0402_25
  round 0.635 smd: 1(-0.508,0) 2(0.508,0)
CC0603_OV
  oval 0.889x1.143 smd: 1(-0.762,0) 2(0.762,0)
CC0805_OV
  oval 0.889x1.524 smd: 1(-0.965,0) 2(0.965,0)
CCE6P8X6P8
  rect 3.556x1.651 smd: 1(-2.35,0) 2(2.35,0)
CON3_PWR_JACK_TH_PJ051A
  round 0.254 hole 2.54 unplated: (-6.3,3.3)
  oval 3.454x1.448 hole 2.819x0.813: 1(0,0) 2(0,8.6) 3(0,3.4)
  oval 3.734x1.448 hole 3.099x0.813: SH1(-7.3,9.5) SH2(-7.3,-0.4)
CON_2RH_10_50
  oval 1.067x1.676 hole 0.787: 1(0,0) 2(0,1.27) 3(1.27,0) 4(1.27,1.27) 5(2.54,0) 6(2.54,1.27) 7(3.81,0) 8(3.81,1.27) 9(5.08,0) 10(5.08,1.27)
CON_HDR_4M_100_TH_RA
  rect 1.651x1.651 hole 1.016: 1(0,0)
  round 1.651 hole 1.016: 2(2.54,0) 3(5.08,0) 4(7.62,0)
CON_MICROAB_10F_25_SM_RA
  rect 1.372x0.406 smd: 1(2.575,-1.3) 2(2.575,-0.65) 3(2.575,0) 4(2.575,0.65) 5(2.575,1.3)
  oval 1.27x1.067 hole 0.864x0.66: 6(2.9,2.225) 7(2.9,-2.225)
  rect 1.905x2.921 smd: 8(-0.1,0)
  custom 0.356x0.356 hole 1.524x0.838: 9(-0.1,4.09) 10(-0.1,-4.09)
CON_SKT1X8_TH
  rect 1.651x1.651 hole 1.016: 1(0,0)
  round 1.651 hole 1.016: 2(0,-2.54) 3(0,-5.08) 4(0,-7.62) 5(0,-10.16) 6(0,-12.7) 7(0,-15.24) 8(0,-17.78)
CON_SKT1X10_TH
  rect 1.651x1.651 hole 1.016: 1(0,0)
  round 1.651 hole 1.016: 2(0,-2.54) 3(0,-5.08) 4(0,-7.62) 5(0,-10.16) 6(0,-12.7) 7(0,-15.24) 8(0,-17.78) 9(0,-20.32) 10(0,-22.86)
DSN0603-2
  rect 0.152x0.254 smd: 1(-0.2,0) 2(0.2,0)
ELECTRODE_SQ_15MM
  rect 15.011x15.011 hole 0.381: 1(-6.35,6.349)
HDR102
  rect 1.524x1.524 hole 1.016: 1(0,0)
  round 1.524 hole 1.016: 2(0,-2.54)
HDR103
  rect 1.524x1.524 hole 1.016: 1(0,0)
  round 1.524 hole 1.016: 2(0,-2.54) 3(0,-5.08)
IND_0402
  round 0.635 smd: 1(-0.508,0) 2(0.508,0)
IND_1608
  rect 0.61x0.813 smd: 1(-0.7,0) 2(0.7,0)
LED6_5X6MM
  rect 2.007x1.6 smd: A1(-2.25,2.1) A2(-2.25,0) A3(-2.25,-2.1) C1(2.25,2.1) C2(2.25,0) C3(2.25,-2.1)
LED_0603
  rect 0.838x0.787 smd: A(-0.775,0) C(0.775,0)
LFPAK5_1P27_5X4
  rect 0.61x1.219 smd: 1(-1.905,-2.975) 2(-0.635,-2.975) 3(0.635,-2.975) 4(1.905,-2.975)
  rect 4.394x4.801 smd: 5(0,1.05)
LQFP48
  rect 1.524x0.305 smd: 1(-4.204,2.752) 2(-4.204,2.252) 3(-4.204,1.751) 4(-4.204,1.251) 5(-4.204,0.751) 6(-4.204,0.25) 7(-4.204,-0.25) 8(-4.204,-0.751) 9(-4.204,-1.251) 10(-4.204,-1.751) 11(-4.204,-2.252) 12(-4.204,-2.752) 25(4.204,-2.752) 26(4.204,-2.252) 27(4.204,-1.751) 28(4.204,-1.251) 29(4.204,-0.751) 30(4.204,-0.25) 31(4.204,0.25) 32(4.204,0.751) 33(4.204,1.251) 34(4.204,1.751) 35(4.204,2.252) 36(4.204,2.752)
  rect 0.305x1.524 smd: 13(-2.752,-4.204) 14(-2.252,-4.204) 15(-1.751,-4.204) 16(-1.251,-4.204) 17(-0.751,-4.204) 18(-0.25,-4.204) 19(0.25,-4.204) 20(0.751,-4.204) 21(1.251,-4.204) 22(1.751,-4.204) 23(2.252,-4.204) 24(2.752,-4.204) 37(2.752,4.204) 38(2.252,4.204) 39(1.751,4.204) 40(1.251,4.204) 41(0.751,4.204) 42(0.25,4.204) 43(-0.25,4.204) 44(-0.751,4.204) 45(-1.251,4.204) 46(-1.751,4.204) 47(-2.252,4.204) 48(-2.752,4.204)
POT3_3352T
  rect 1.651x1.651 hole 1.016: 1(0,0)
  round 1.651 hole 1.016: 2(2.54,0) 3(5.08,0)
QFN32_0P5_5X5_S146EP
  oval 0.813x0.305 smd: 1(-2.45,1.75) 2(-2.45,1.25) 3(-2.45,0.75) 4(-2.45,0.25) 5(-2.45,-0.25) 6(-2.45,-0.75) 7(-2.45,-1.25) 8(-2.45,-1.75) 17(2.45,-1.75) 18(2.45,-1.25) 19(2.45,-0.75) 20(2.45,-0.25) 21(2.45,0.25) 22(2.45,0.75) 23(2.45,1.25) 24(2.45,1.75)
  oval 0.305x0.813 smd: 9(-1.75,-2.45) 10(-1.25,-2.45) 11(-0.75,-2.45) 12(-0.25,-2.45) 13(0.25,-2.45) 14(0.75,-2.45) 15(1.25,-2.45) 16(1.75,-2.45) 25(1.75,2.45) 26(1.25,2.45) 27(0.75,2.45) 28(0.25,2.45) 29(-0.25,2.45) 30(-0.75,2.45) 31(-1.25,2.45) 32(-1.75,2.45)
  rect 3.708x3.708 smd: 33(0,0)
QFN32_S142EP
  custom 0.07x0.07 smd: 1(-2.4,1.751) 2(-2.4,1.251) 3(-2.4,0.751) 4(-2.4,0.25) 5(-2.4,-0.25) 6(-2.4,-0.751) 7(-2.4,-1.251) 8(-2.4,-1.751) 9(-1.751,-2.4) 10(-1.251,-2.4) 11(-0.751,-2.4) 12(-0.25,-2.4) 13(0.25,-2.4) 14(0.751,-2.4) 15(1.251,-2.4) 16(1.751,-2.4) 17(2.4,-1.751) 18(2.4,-1.251) 19(2.4,-0.751) 20(2.4,-0.25) 21(2.4,0.25) 22(2.4,0.751) 23(2.4,1.251) 24(2.4,1.751) 25(1.751,2.4) 26(1.251,2.4) 27(0.751,2.4) 28(0.25,2.4) 29(-0.25,2.4) 30(-0.751,2.4) 31(-1.251,2.4) 32(-1.751,2.4)
  rect 3.607x3.607 smd: 33(0,0)
RC0402_25
  round 0.635 smd: 1(-0.508,0) 2(0.508,0)
RC0603_OV
  oval 0.889x1.143 smd: 1(-0.762,0) 2(0.762,0)
RC0805_OV
  oval 0.889x1.524 smd: 1(-0.965,0) 2(0.965,0)
RC1206_OV
  oval 1.016x1.778 smd: 1(-1.524,0) 2(1.524,0)
SC_75
  rect 0.483x0.635 smd: 1(-0.5,-0.647) 2(0.5,-0.647) 3(0,0.647)
SH0603
  rect 0.991x0.813 smd: 1(-0.8,0) 2(0.8,0)
SKT2X8_TH_SSQ
  rect 1.524x1.524 hole 1.016: 1(0,0)
  round 1.524 hole 1.016: 2(-2.54,0) 3(0,-2.54) 4(-2.54,-2.54) 5(0,-5.08) 6(-2.54,-5.08) 7(0,-7.62) 8(-2.54,-7.62) 9(0,-10.16) 10(-2.54,-10.16) 11(0,-12.7) 12(-2.54,-12.7) 13(0,-15.24) 14(-2.54,-15.24) 15(0,-17.78) 16(-2.54,-17.78)
SO8_1P27_4X5
  rect 1.6x0.61 smd: 1(-2.7,1.905) 2(-2.7,0.635) 3(-2.7,-0.635) 4(-2.7,-1.905) 5(2.7,-1.905) 6(2.7,-0.635) 7(2.7,0.635) 8(2.7,1.905)
SOD-128
  rect 1.397x2.108 smd: A(-2.2,0) C(2.2,0)
SON20_0P5_3P6X5P6
  rect 0.305x0.94 smd: 1(-2.25,-1.65) 2(-1.75,-1.65) 3(-1.25,-1.65) 4(-0.75,-1.65) 5(-0.25,-1.65) 6(0.25,-1.65) 7(0.75,-1.65) 8(1.25,-1.65) 9(1.75,-1.65) 10(2.25,-1.65) 11(2.25,1.65) 12(1.75,1.65) 13(1.25,1.65) 14(0.75,1.65) 15(0.25,1.65) 16(-0.25,1.65) 17(-0.75,1.65) 18(-1.25,1.65) 19(-1.75,1.65) 20(-2.25,1.65)
  rect 4.851x1.854 smd: 21(0,0)
SOT23-6_A
  rect 1.219x0.61 smd: 1(-1.25,0.95) 2(-1.25,0) 3(-1.25,-0.95) 4(1.25,-0.95) 5(1.25,0) 6(1.25,0.95)
SOT23_5S
  rect 0.686x0.991 smd: 1(-0.953,-1.295) 2(0,-1.295) 3(0.953,-1.295) 4(0.953,1.295) 5(-0.953,1.295)
SOT891_6P_0P35_1P05X1P05
  rect 0.635x0.152 smd: 1(-0.412,0.35) 2(-0.412,0) 3(-0.412,-0.35) 4(0.412,-0.35) 5(0.412,0) 6(0.412,0.35)
SOT-563_6P_0P5_SMT
  rect 0.61x0.279 smd: 1(-0.9,0.5) 2(-0.9,0) 3(-0.9,-0.5) 4(0.9,-0.5) 5(0.9,0) 6(0.9,0.5)
SSOP8_DCU
  rect 0.279x1.219 smd: 1(-0.75,-1.499) 2(-0.25,-1.499) 3(0.25,-1.499) 4(0.75,-1.499) 5(0.75,1.499) 6(0.25,1.499) 7(-0.25,1.499) 8(-0.75,1.499)
SW4_SPST_4P8X3P6_2P5
  rect 1.499x0.991 smd: 1(2.575,0.85) 2(2.575,-0.85) 3(-2.575,0.85) 4(-2.575,-0.85)
TESTPOINT_135_070MIL
  rect 3.429x1.778 smd: 1(0,0)
TP_TH_063
  round 2.311 hole 1.6: 1(0,0)
TPAD_030
  round 0.762 smd: 1(0,0)
UDFN6_1X1P5MM
  rect 0.584x0.305 smd: 1(-0.418,0.5)
  rect 0.508x0.305 smd: 2(-0.38,0) 3(-0.38,-0.5) 4(0.38,-0.5) 5(0.38,0) 6(0.38,0.5)
unnamed#2
  round 0.254 hole 3.175 unplated: (0,0)
XQFN8_1P45X1P25MM
  rect 0.787x0.203 smd: 1(-0.75,0)
  rect 0.203x0.711 smd: 2(-0.4,-0.65) 3(0,-0.65) 4(0.4,-0.65) 6(0.4,0.65) 7(0,0.65) 8(-0.4,0.65)
  rect 0.711x0.203 smd: 5(0.75,0)
XTAL2_3P3X2P6
  rect 1.6x2.718 smd: 1(-1,0) 2(1,0)
XTAL3_3P35X1P45_SM
  rect 0.406x2.108 smd: 1(1.2,0) 2(0,0) 3(-1.2,0)

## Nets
GND: C1.2 C2.2 C3.2 C4.2 C5.2 C6.2 C7.2 C8.2 C9.2 C10.2 C11.2 C12.2 C16.2 C17.2 C18.2 C19.2 C20.2 C21.2 C22.2 C23.2 C24.2 C25.2 C26.2 C27.2 C28.2 C40.2 C47.2 C59.2 C126.2 C127.2 C128.2 C129.2 C140.2 C143.2 C144.2 C533.2 C535.2 C536.2 C542.2 C543.2 C545.2 C546.2 C547.2 C548.2 C549.2 C550.2 C551.2 C552.2 C553.2 C554.2 C555.2 C556.2 C557.2 C558.2 D17.1(C1) D18.1(C1) D19.1(C1) D59.2(ANODE2) D60.2(ANODE2) GND1.1 GND2.1 GND3.1 GND4.1 J2.7 J3.11(A6) J3.13(A7) J7.5(GND) J11.4 J12.3(A2) J12.5(A3) J13.4 J14.3(A2) J14.5(A3) J16.2 J16.3 J16.SH1(SHIELD1) J16.SH2(SHIELD2) L2.2 Q6.2(EMITTER) Q7.2(EMITTER) Q8.2(EMITTER) Q9.2(EMITTER) Q11.1(E1) R13.3(B) R16.2 R20.2 R31.2 R44.2 R51.2 R62.2 R68.2 R74.2 R170.1 R575.2 R599.2 R600.2 R602.2 R605.2 R661.2 R731.2 R734.2 SW5.1 SW5.3 SW9.2 SW9.4 U1.4(GND) U2.4(GND) U2.5(DIR) U4.2(GND) U7.2(GND) U8.2(VSS1) U8.8(VSSA) U8.33(EPAD) U9.2(GND) U10.2(GND) U11.2(GND) U15.2(GND) U19.1(GND1) U19.4(GND2) U19.16(GND3) U19.19(GND4) U19.21(EP) U21.5(GND) U26.4(GND) U32.4(GND) U33.4(GND) U34.4(GND) U36.7(VSS1) U36.30(VSS2) U37.4(VSS_1) U37.20(VSS_2) U37.33(E-PAD) Y1.2
P3V3: C24.1 C548.1 C557.1 J3.7(A4) J10.1 R737.2 TP510.1(PIN1) TS5.1
P3V3_SDA: C3.1 C6.1 C7.1 C10.1 C12.1 C18.1 C19.1 C26.1 J12.1(A1) R1.2 R3.1 R12.1 R15.1 R30.1 R39.2 R42.1 R52.1 R60.1 R77.1 R607.1 R627.2 U1.1(VCCA) U2.1(VCCA) U4.1(VCCA) U7.1(VCCA) U8.1(VDD1) U8.7(VDDA) U8.11(VBAT) U9.5(VCC) U10.1(VCCA)
P5V0: C21.1 C22.1 C550.1 C558.1 J3.9(A5) J10.3 J107.2 R56.1 R95.2 R96.2 R97.2 R169.1 R624.1 R729.2 TP509.1(PIN1) TP527.1
P5V0_SDA_USB_CONN_VBUS: D17.2(C2) J7.1(VBUS) L1.1
P5V_SBC: C27.1 C547.1 J107.1 R535.1 R536.1 R562.1 R571.1 R572.1 R576.1 R594.1 R617.1 R618.1 R619.1 R620.1 R621.1 R622.1 TP525.1(PIN1) TS8.1 U19.5(V1) U26.1(VCCA) U32.1(VCCA) U33.1(VCCA) U34.1(VCCA)
P5V_SDA: C11.1 C15.1 C25.1 L1.2 R14.1 R57.1 R70.1 U8.6(VREGIN) U11.1(VIN)
P5V_SDA_PSW: J107.3 U11.6(VOUT)
VBATT: C544.1 C555.1 D9.A J3.1(A1) J3.15(A8) J11.2 J16.1 R606.2 TP507.1(PIN1) TP522.1
VDD: C553.1 J10.2 J14.1(A1) J15.1 Q10.4(E2) R117.1 R121.1 R573.1 R574.1 R593.1 R604.1 R623.1 R733.1 SH1.2 SW2.2 SW2.4 SW3.2 SW3.4 TP4.1 TP9.1 TP511.1(PIN1) TPAD99.1(PIN1) TS1.1
VDD_MCU: C129.1 C140.1 C143.1 C144.1 D59.1(ANODE1) J15.2 L512.2 R117.2 R300.1 TP533.1(PIN1) TS2.1 U36.5(VDD1) U36.31(VDD2) U37.3(VDD_1) U37.21(VDD_2)
VDD_PERH: C554.1 C556.1 J3.3(A2) R530.1 R538.1 R570.1 R593.2 R609.1 R610.1 R611.1 R612.1 R613.1 R614.1 R615.1 R616.1 R674.1 R712.1 R713.1 TP526.1 TP541.1(PIN1) TS6.1 U26.8(VCCB) U32.8(VCCB) U33.8(VCCB) U34.8(VCCB)
VDDA_MCU: C542.1 C543.1 D60.1(ANODE1) L512.1 R300.2 R569.1 TP534.1(PIN1) TP545.1(PIN1) TS3.1 U36.6(VDDA)
ADC_POT: C549.1 R597.2 R670.1 R711.2 R727.1 R750.1 TP528.1(PIN1)
AREF: J2.8 R569.2
BTN0: C16.1 R596.2 R659.2 TP530.1(PIN1)
BTN1: C28.1 R595.2 R660.2 TP529.1(PIN1)
CAN_HI: J13.1 R92.1 TP504.1(PIN1) U19.18(CANH)
CAN_LO: J13.2 R98.2 TP503.1(PIN1) U19.17(CANL)
EXTAL: C126.1 R88.1 R91.1 Y3.1
JTAG_TCLK/SWD_CLK: J14.4(B2) R575.1 R626.1 TP536.1(PIN1) U36.46(PTC4/FTM1_CH0/RTC_CLKOUT/FTM1_Q) U37.30(PTC4/FTM1_CH0/RTC_CLKOUT/FTM1_Q)
JTAG_TDI: R120.2 R632.1 TP538.1(PIN1)
JTAG_TDO: R119.2 R645.1 TP537.1(PIN1)
JTAG_TMS/SWD_DIO: J14.2(B1) R121.2 R625.1 TP535.1(PIN1) U36.48(PTA4/CMP0_OUT/JTAG_TMS/SWD_DIO) U37.32(PTA4/CMP0_OUT/JTAG_TMS/SWD_DIO)
LEDRGB_BLUE: D11.C3(CATHODE3) Q8.3(COLLECTOR) TP28.1(PIN1)
LEDRGB_GREEN: D11.C2(CATHODE2) Q7.3(COLLECTOR) TP29.1(PIN1)
LEDRGB_RED: D11.C1(CATHODE1) Q6.3(COLLECTOR) TP30.1(PIN1)
LIN: C17.1 J11.1 R80.1 R171.1 TP18.1(PIN1) TS4.1 U21.6(LIN)
LIN_RX: R538.2 R664.1 R679.2 TP519.1(PIN1) U21.1(RXD)
LIN_SLP: R530.2 R661.1 R672.1 TP521.1(PIN1) U21.2(S\L\P\)
LIN_TX: R570.2 R665.1 R680.2 TP520.1(PIN1) U21.4(TXD)
LVLRST_EN: R1.1 U1.5(OE)
MIC2005_CSLEW: C15.2 U11.5(CSLEW)
POWER_EN: R69.1 U8.31(ADC0_SE7B/PTD6/SPI0_PCS3/UART0_)
PTA0: R673.1 R718.1 R742.1
PTA0_MCU: R670.2 R673.2 U36.38(PTA0/LPI2C0_SCLS/FXIO_D2/LPUART) U37.26(PTA0/LPI2C0_SCLS/FXIO_D2/LPUART)
PTA1: R719.1 R741.1 R743.1
PTA1_MCU: R741.2 U36.37(PTA1/FTM1_CH1/LPI2C0_SDAS/FXIO_) U37.25(PTA1/FTM1_CH1/LPI2C0_SDAS/FXIO_)
PTA2: R675.1 U36.36(PTA2/LPI2C0_SDA/FXIO_D4/LPUART0) U37.24(PTA2/LPI2C0_SDA/FXIO_D4/LPUART0)
PTA3: R676.1 U36.35(PTA3/LPI2C0_SCL/FXIO_D5/LPUART0) U37.23(PTA3/LPI2C0_SCL/FXIO_D5/LPUART0)
PTA7: J4.1(A1) R671.1 R749.2 R751.2
PTA7_MCU: R671.2 R672.2 R747.2 R750.2 U36.29(PTA7/FTM0_FLT2/RTC_CLKIN/LPUART) U37.19(PTA7/FTM0_FLT2/RTC_CLKIN/LPUART)
PTA10_MCU: R645.2 U36.44(PTA10/FTM1_CH4/FXIO_D0/JTAG_TDO) U37.28(PTA10/FTM1_CH4/FXIO_D0/JTAG_TDO)
PTA11: R669.1 R751.1 R752.1
PTA11_MCU: R668.2 R669.2 U36.43(PTA11/FTM1_CH5/FXIO_D1/CMP0_RRT) U37.27(PTA11/FTM1_CH5/FXIO_D1/CMP0_RRT)
PTA12: J1.4 U36.42(PTA12/FTM1_CH6)
PTA13: J1.3 U36.41(PTA13/FTM1_CH7)
PTB0: R662.1 R748.1 R754.1
PTB0_MCU: R662.2 R666.2 U36.26(PTB0/LPUART0_RX/LPSPI0_PCS0/LPT) U37.18(PTB0/LPUART0_RX/LPSPI0_PCS0/LPT)
PTB1: R663.1 R749.1 R753.1
PTB1_MCU: R663.2 R667.2 R727.2 U36.25(PTB1/LPUART0_TX/LPSPI0_SOUT/TCL) U37.17(PTB1/LPUART0_TX/LPSPI0_SOUT/TCL)
PTB2: J2.6 R642.1
PTB2_MCU: R638.2 R642.2 U36.24(PTB2/FTM1_CH0/LPSPI0_SCK/FTM1_Q) U37.16(PTB2/FTM1_CH0/LPSPI0_SCK/FTM1_Q)
PTB3: J2.5 R641.1
PTB3_MCU: R637.2 R641.2 U36.23(PTB3/FTM1_CH1/LPSPI0_SIN/FTM1_Q) U37.15(PTB3/FTM1_CH1/LPSPI0_SIN/FTM1_Q)
PTB4: J2.4 R640.1
PTB4_MCU: R636.2 R640.2 U36.15(PTB4/FTM0_CH4/LPSPI0_SOUT/TRGMU) U37.11(PTB4/FTM0_CH4/LPSPI0_SOUT/TRGMU)
PTB5: J2.3 R639.1
PTB5_MCU: R635.2 R639.2 U36.14(PTB5/FTM0_CH5/LPSPI0_PCS1/LPSPI) U37.10(PTB5/FTM0_CH5/LPSPI0_PCS1/LPSPI)
PTB6: J3.6(B3) R644.1 R716.1
PTB6_MCU: R84.2 R644.2 U36.9(PTB6/LPI2C0_SDA/XTAL) U37.6(PTB6/LPI2C0_SDA/XTAL)
PTB7: J3.8(B4) R643.1 R717.1
PTB7_MCU: R88.2 R643.2 U36.8(PTB7/LPI2C0_SCL/EXTAL) U37.5(PTB7/LPI2C0_SCL/EXTAL)
PTB13: R681.1 U36.32(PTB13/FTM0_CH1)
PTC1: R687.1 R739.2
PTC2: J2.1 R678.1
PTC2_MCU: R664.2 R678.2 U36.17(PTC2/FTM0_CH2/CAN0_RX/LPUART0_R) U37.13(PTC2/FTM0_CH2/CAN0_RX/LPUART0_R)
PTC3: J2.2 R677.1
PTC3_MCU: R665.2 R677.2 U36.16(PTC3/FTM0_CH3/CAN0_TX/LPUART0_T) U37.12(PTC3/FTM0_CH3/CAN0_TX/LPUART0_T)
PTC5_MCU: R632.2 U36.45(PTC5/RTC_CLKOUT/JTAG_TDI) U37.29(PTC5/RTC_CLKOUT/JTAG_TDI)
PTC6: J4.2(B1) R683.2
PTC6_MCU: R679.1 R683.1 U36.40(PTC6/LPUART1_RX/FTM1_QD_PHB)
PTC7: J4.4(B2) R684.2
PTC7_MCU: R680.1 R684.1 U36.39(PTC7/LPUART1_TX/FTM1_QD_PHA)
PTC8: R702.1 R745.1 U36.28(PTC8/LPUART1_RX/FTM1_FLT0/LPUAR)
PTC9: R685.1 R703.1 U36.27(PTC9/LPUART1_TX/FTM1_FLT1/LPUAR)
PTC14: J4.7(A4) U36.22(PTC14/FTM1_CH2/TRGMUX_IN9/ADC0_)
PTC15: J4.9(A5) R746.1 U36.21(PTC15/FTM1_CH3/TRGMUX_IN8/ADC0_)
PTC16: R686.1 R744.1 U36.20(PTC16/FTM1_FLT2/ADC0_SE14)
PTD0: J1.5 U36.2(PTD0/FTM0_CH2/FXIO_D0/TRGMUX_OU)
PTD1: J1.6 U36.1(PTD1/FTM0_CH3/FXIO_D1/TRGMUX_OU)
PTD2: J1.7 U36.34(PTD2/FXIO_D4/FXIO_D6/TRGMUX_IN5)
PTD3: J3.16(B8) R696.2
PTD3_MCU: R659.1 R696.1 U36.33(PTD3/FXIO_D5/FXIO_D7/TRGMUX_IN4) U37.22(PTD3/FXIO_D5/FXIO_D7/TRGMUX_IN4)
PTD5: J4.10(B5) R697.2
PTD5_MCU: R660.1 R697.1 U36.18(PTD5/LPTMR0_ALT2/TRGMUX_IN7) U37.14(PTD5/LPTMR0_ALT2/TRGMUX_IN7)
PTD15: R657.2 R693.1
PTD15_MCU: R654.1 R657.1 U36.11(PTD15/FTM0_CH0/LPSPI0_SCK) U37.8(PTD15/FTM0_CH0/LPSPI0_SCK)
PTD16: R656.2 R694.1
PTD16_MCU: R653.1 R656.1 U36.10(PTD16/FTM0_CH1/LPSPI0_SIN/CMP0_) U37.7(PTD16/FTM0_CH1/LPSPI0_SIN/CMP0_)
PTE4: J3.10(B5) R651.2
PTE4_MCU: R649.1 R651.1 U36.4(PTE4/CAN0_RX/FXIO_D6) U37.2(PTE4/CAN0_RX/FXIO_D6)
PTE5: J3.12(B6) R652.2
PTE5_MCU: R650.1 R652.1 U36.3(PTE5/TCLK2/CAN0_TX/FXIO_D7) U37.1(PTE5/TCLK2/CAN0_TX/FXIO_D7)
PTE8: R658.2 R695.1
PTE8_MCU: R655.1 R658.1 U36.13(PTE8/FTM0_CH6/CMP0_IN3) U37.9(PTE8/FTM0_CH6/CMP0_IN3)
PTE9: J1.8 U36.12(PTE9/FTM0_CH7)
RESET_S32K: J14.10(B5) J104.1 R4.2 R5.2 R574.2 R585.2 R715.1 R732.1 TP539.1(PIN1) TS7.1 U1.7(B1) U36.47(PTA5/TCLK1/R\E\S\E\T\) U37.31(PTA5/TCLK1/R\E\S\E\T\)
RGB_BLUE: R603.1 R655.2 TPAD97.1(PIN1)
RGB_GREEN: R601.1 R654.2 TPAD95.1(PIN1)
RGB_RED: R598.1 R653.2 TPAD94.1(PIN1)
SBC_CAN_RX: R588.2 R649.2
SBC_CAN_RX_LS: R580.1 TP512.1(PIN1) U19.7(RXD)
SBC_CAN_TX: R587.2 R650.2
SBC_CAN_TX_LS: R579.1 TP513.1(PIN1) U19.2(TXD)
SBC_CS: R592.2 R635.1
SBC_CS_LS: R584.1 TP517.1(PIN1) U19.20(S\C\S\)
SBC_LIMP: R609.2 R668.1 U32.6(B2)
SBC_LIMP_LS: R536.2 R578.1 TP505.1(PIN1) U19.11(L\I\M\P\)
SBC_MISO: R591.2 R637.1
SBC_MISO_LS: R583.1 TP516.1(PIN1) U19.9(SDO)
SBC_MOSI: R590.2 R636.1
SBC_MOSI_LS: R582.1 TP515.1(PIN1) U19.3(SDI)
SBC_RST_LS: R577.1 R594.2 TP506.1(PIN1) U19.8(R\S\T\)
SBC_SCK: R589.2 R638.1
SBC_SCK_LS: R581.1 TP514.1(PIN1) U19.10(SCK)
SDA_EXTAL: C23.1 U8.17(EXTAL0/PTA18/FTM0_FLT2/FTM_CLKI) Y1.3
SDA_JTAG_TCLK: J12.4(B2) U8.12(JTAG_TCLK/SWD_CLK/EZP_CLK/TSI0_)
SDA_JTAG_TDI: J12.8(B4) U8.13(JTAG_TDI/EZP_DI/TSI0_CH2/PTA1/U)
SDA_JTAG_TDO: J12.6(B3) U8.14(JTAG_TDO/TRACE_SWO/EZP_DO/TSI0_)
SDA_JTAG_TMS: J12.2(B1) R77.2 U8.15(JTAG_TMS/SWD_DIO/TSI0_CH4/PTA3/)
SDA_LED: D2.C(CATHODE) U8.29(PTD4/SPI0_PCS1/U\A\R\T\0\_\R\T\)
SDA_LED_R: D2.A(ANODE) R12.2
SDA_RST: J12.10(B5) R57.2 R62.1 TP12.1(PIN1) U8.19(R\E\S\E\T\)
SDA_RST_LED: D1.C(CATHODE) Q11.6(C1)
SDA_RST_TGTMCU_B: R701.1 U8.21(ADC0_SE9/TSI0_CH6/PTB1/I2C0_SDA)
SDA_RST_TGTMCU_J_B: J104.3 R3.2 R5.1 R701.2 U1.2(A1)
SDA_RX_EN: R15.2 R16.1 U4.5(DIR)
SDA_SPI0_CS: R38.2 TP7.1(PIN1) U8.23(ADC0_SE4B/CMP1_IN0/TSI0_CH15/PT)
SDA_SPI0_RST_B: R41.2 TP8.1(PIN1) U8.22(ADC0_SE15/TSI0_CH14/PTC1/SPI0_P)
SDA_SPI0_SCK: U8.26(PTC5/SPI0_SCK/LPTMR0_ALT2/I2S0_) U10.3(A)
SDA_SPI0_SIN: U2.3(2A) U8.28(CMP0_IN1/PTC7/SPI0_SIN/USB_SOF_)
SDA_SPI0_SOUT: U7.3(A) U8.27(CMP0_IN0/PTC6/SPI0_SOUT/PDB0_EX)
SDA_SWD_EN: R41.1 R47.1 U9.6(Y1)
SDA_SWD_EN_B: R49.2 U8.16(N\M\I\/E\Z\P\_\C\S\/TSI0_CH5/PT)
SDA_SWD_EN_B_R: R42.2 R49.1 U9.1(A1)
SDA_SWD_EN_R: R47.2 R51.1 R52.2 U10.5(DIR)
SDA_SWD_OE: R35.1 R38.1 U9.4(Y2)
SDA_SWD_OE_B: R32.2 U8.20(ADC0_SE8/TSI0_CH0/PTB0/I2C0_SCL)
SDA_SWD_OE_B_R: R32.1 R39.1 U9.3(A2)
SDA_SWD_OE_R: R30.2 R31.1 R35.2 U7.5(DIR)
SDA_USB_CONN_DN: D19.2(C2) J7.2(D-) R25.1
SDA_USB_CONN_DP: D18.2(C2) J7.3(D+) R21.1
SDA_USB_DN: R25.2 U8.4(USB0_DM)
SDA_USB_DP: R21.2 U8.3(USB0_DP)
SDA_USB_P5V_SENSE: R14.2 R20.1 U8.30(ADC0_SE6B/PTD5/SPI0_PCS2/U\A\R\)
SDA_USBSHIELD: J7.6(SHELL1) J7.7(SHELL2) J7.8(SHELL3) J7.9(SHELL4) J7.10(SHELL5) L2.1
SDA_VOUT33: C9.1 R627.1 U8.5(VOUT33)
SDA_XTAL: C20.1 U8.18(XTAL0/PTA19/FTM1_FLT0/FTM_CLKIN) Y1.1
SW1_RST_B: C1.1 J104.2 SW5.2 SW5.4
SWD_CLK_TGTMCU_BUF: R626.2 U10.4(B)
SWD_DIO_TGTMCU_BUF: R625.2 U2.6(2B) U7.4(B)
TC_EXTAL_TP: TP11.1(PIN1) U8.10(EXTAL32)
TC_SDA_USB_ID_TP: J7.4(ID) TP6.1(PIN1)
TC_XTAL_TP: TP10.1(PIN1) U8.9(XTAL32)
TOUCH_PTA7: R527.2 R528.2 R747.1
TOUCH_PTC1: R172.2 R525.2 R740.2
TOUCH_PTC15: C535.1 R528.1 R746.2
TOUCH_PTC16: C533.1 R525.1 R744.2
TP_2102_A: R607.2 U1.3(A2)
TP_2102_B: R608.2 U1.6(B2)
UART1_RX_TGTMCU_BUF: R24.1 U4.4(B)
UART1_RX_TGTMCU_R: U4.3(A) U8.25(PTC4/SPI0_PCS0/UART1_TX/FTM0_CH)
UART1_TX_TGTMCU_BUF: R18.1 U2.7(1B)
UART1_TX_TGTMCU_R: U2.2(1A) U8.24(CMP1_IN1/PTC3/SPI0_PCS1/UART1_R)
UART_RX: R24.2 R666.1
UART_TX: R18.2 R667.1
V_TGTMCU: C2.1 C4.1 C8.1 R4.1 R608.1 SH1.1 U1.8(VCCB) U2.8(VCCB) U4.6(VCCB) U7.6(VCCB) U10.6(VCCB)
VSUP: C47.1 C128.1 C546.1 C552.1 D9.C J108.2 Q1.1(EMITTER1) Q1.2(EMITTER2) Q1.3(EMITTER3) R537.1 TP508.1(PIN1) U19.14(BAT) U21.7(VBAT)
VTRG_EN: R68.1 R69.2 R70.2 U11.3(ENABLE)
VTRG_FAULT_B: R60.2 U8.32(PTD7/CMT_IRO/UART0_TX/FTM0_CH7/) U11.4(F\A\U\L\T\)
XTAL: C127.1 R84.1 R91.2 Y3.2
N20108236: R737.1 U15.5(VOUT)
N20187731: D11.A3(ANODE3) R95.1
N20187747: D11.A2(ANODE2) R96.1
N20224636: C5.1 R13.2(WIPER) R597.1 TP5.1(PIN1)
N20296072: R44.1 R596.1 SW2.1 SW2.3 TP532.1(PIN1)
N20296289: R74.1 R595.1 SW3.1 SW3.3 TP531.1(PIN1)
N20296614: D11.A1(ANODE1) R97.1
N20342040: J2.10 R712.2 R717.2 R718.2
N20342083: J2.9 R713.2 R716.2 R719.2
N20408163: R169.2 R170.2 TP540.1(PIN1) U15.3(EN)
N20408770: C59.1 U15.4(BYP)
N20447644: J1.1 R675.2
N20447648: J1.2 R676.2
N20483097: J3.5(A3) R715.2
N20487701: R527.1 SW8.1
N20498073: Q1.4(BASE) TP524.1(PIN1) U19.15(VEXCTRL)
N20519466: C536.1 TP544.1(PIN1) U19.13(V2)
N20529258: D6.C R80.2 R171.2
N20532266: Q1.5(COLLECTOR) R535.2 TP523.1(PIN1) U19.6(VEXCC)
N20533540: R172.1 SW7.1
N20537015: C551.1 R537.2 SW9.1 SW9.3 TP518.1(PIN1) U19.12(WAKE)
N20537534: D6.A J108.1
N20615858: R590.1 R612.2 U26.6(B2)
N20615860: R589.1 R613.2 U26.7(B1)
N20628442: R585.1 R616.2 U32.7(B1)
N20629726: R577.2 U32.2(A1)
N20726302: R578.2 U32.3(A2)
N20727622: R562.2 U32.5(OE)
N20728836: C40.1 R92.2 R98.1
N20751108: R571.2 U33.5(OE)
N20751111: R587.1 R610.2 U33.7(B1)
N20751112: R588.1 R611.2 U33.6(B2)
N20754157: R572.2 U26.5(OE)
N20757133: R591.1 R615.2 U34.7(B1)
N20757185: R592.1 R614.2 U34.6(B2)
N20757257: R576.2 U34.5(OE)
N20757373: R579.2 R617.2 U33.2(A1)
N20757398: R580.2 R618.2 U33.3(A2)
N20757820: R581.2 R619.2 U26.2(A1)
N20757845: R582.2 R620.2 U26.3(A2)
N20758005: R583.2 R621.2 U34.2(A1)
N20758031: R584.2 R622.2 U34.3(A2)
N20759089: D3.A(ANODE) R56.2
N20766439: J14.6(B3) R119.1 R573.2
N20766441: J14.8(B4) R120.1 R623.2
N20788275: Q6.1(BASE) R598.2 R599.1 TPAD93.1(PIN1)
N20788431: Q7.1(BASE) R600.1 R601.2 TPAD96.1(PIN1)
N20788562: Q8.1(BASE) R602.1 R603.2 TPAD98.1(PIN1)
N20797138: Q9.1(BASE) R604.2 R605.1 TPAD100.1(PIN1)
N20798434: D3.C(CATHODE) Q9.3(COLLECTOR)
N20799004: J13.3 R606.1
N20829527: R624.2 U15.1(VIN)
N20881340: R13.1(A) R674.2
N20904035: R711.1 R739.1 R740.1 U36.19(PTC1/FTM0_CH1/FTM1_CH7/ADC0_SE9)
N20906563: J4.13(A7) R685.2 R743.2
N20906569: J4.11(A6) R686.2
N20906587: J4.5(A3) R687.2
N20906597: J4.3(A2) R742.2 R745.2
N20906792: J4.15(A8) R681.2 R748.2
N20910223: J4.8(B4) R703.2
N20910227: J4.6(B3) R702.2
N20911130: J4.12(B6) R693.2
N20911135: J4.14(B7) R694.2
N20911140: J4.16(B8) R695.2
N20917588: J3.2(B1) R754.2
N20917593: J3.4(B2) R753.2
N20917620: J3.14(B7) R752.2
N20992665: D1.A(ANODE) R729.1
N20992701: Q10.3(C2) R730.1 R731.1
N20992723: Q10.5(B2) R732.2 R733.2
N20992733: Q11.2(B1) R730.2 R734.1
N207179701: C544.2 C545.1
N207665286: J14.7(A4) TP542.1(PIN1)
N207665288: J14.9(A5) TP543.1(PIN1)

Pads without a net: J11 3; J12 7 9; Q10 1 2 6; Q11 3 4 5; U21 3 8

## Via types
v1: diameter 0.508, hole 0.254, TOP to BOTTOM, 601 vias
v2: diameter 0.61, hole 0.356, TOP to BOTTOM, 27 vias

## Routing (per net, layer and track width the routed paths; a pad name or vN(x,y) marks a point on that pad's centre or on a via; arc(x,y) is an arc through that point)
GND: length 562.9
  TOP w0.152: D19.1 v1(8.9,42.94) ; U9.2 v1(36.02,39.65) ; D18.1 v1(8.91,44.46) ; D17.1 v1(8.98,41.45)
  TOP w0.203: U33.4 50.92,21.87 v1(50.97,21.91) ; U26.4 39.96,24.03 v1(40.04,23.94) ; v1(7.15,51.83) 7.31,51.67 U1.4 ; U34.4 v1(40.23,18.18) ; U32.4 44.68,21.58 44.95,21.32 45.38,21.32 v1(45.72,20.98)
  TOP w0.254: v1(24.55,32.47) 23.44,33.58 Y1.2 ; v1(79.38,28.69) 79.37,28.69 U36.30 ; C19.2 32.54,36.03 ; C19.2 32.03,35.52 ; C19.2 32.03,36.54 ; 94.96,2.2 R599.2 93.94,2.2 ; 2.88,51.99 C2.2 ; C2.2 3.39,52.5 ; C2.2 3.9,51.99 ; U21.5 22.56,27.2 ; U21.5 23.55,26.7 ; U21.5 22.56,26.21 ; 10.5,21.37 C40.2 9.74,22.01 ; 15.08,38.99 C12.2 14.32,38.36 ; 86.51,29.53 C533.2 85.88,28.76 ; 106.64,44.74 C5.2 107.15,45.25 ; 110.24,30.28 C16.2 109.23,30.28 ; U4.2 v1(27.85,44.44) ; C4.2 8.63,48.72 v1(8.86,48.95) ; 18.23,15.37 v1(18.23,17.99) 18.23,20.61 ; 95.07,4.49 Q7.2 ; Q7.2 95.58,4.92 ; Q7.2 95.58,4.06 ; Q7.2 96.09,4.49 ; 24.17,53.43 SW5.1 ; SW5.1 26.06,53.43 ; SW5.1 25.12,52.75 ; SW5.1 25.12,54.12 ; C1.2 25.43,50.4 ; C1.2 25.43,49.38 ; C1.2 25.94,49.89 ; 34.63,10.07 C556.2 35.14,9.56 ; 11.07,49.99 R731.2 10.56,50.5 ; 48.6,9.69 C558.2 47.59,9.69 ; R20.2 21.7,44.9 ; R20.2 21.19,44.39 ; R20.2 22.21,44.39 ; R20.2 21.7,43.88 ; 110.24,24.99 R74.2 109.23,24.99 ; 11.14,13.12 C551.2 11.14,11.59 ; 95.07,2.2 Q6.2 ; Q6.2 95.58,2.64 ; Q6.2 96.09,2.2 ; Q6.2 95.58,1.77 ; 59.26,29.84 C542.2 ; C542.2 59.89,28.89 ; C542.2 59.89,30.8 ; R605.2 47.71,14.39 ; R605.2 47.21,13.88 ; R605.2 46.7,14.39 ; 8.85,40.28 C11.2 9.35,40.79 ; 33.11,36.61 C550.2 32.6,36.11 ; J2.7 37.55,53.38 ; J2.7 36.54,54.39 ; J2.7 35.52,53.38 ; J2.7 36.54,52.36 ; SW5.3 20.91,53.43 ; SW5.3 19.96,52.75 ; SW5.3 19.02,53.43 ; SW5.3 19.96,54.12 ; C20.2 22.32,35.88 ; C20.2 22.32,34.86 ; C20.2 22.19,35.5 v1(21.48,35.5) 21.48,34.84 C23.2 ; C20.2 22.83,35.37 ; D19.1 8.34,42.55 ; 63.47,32.54 C144.2 ; C144.2 64.11,33.49 ; C144.2 64.11,31.58 ; 23.84,17.18 C547.2 ; 9.03,32.23 U11.2 ; 21.14,34.67 C23.2 ; C23.2 21.64,34.16 ; C23.2 22.15,34.67 ; 31.97,42.71 R31.2 32.47,42.2 ; C22.2 34.12,36.61 ; U2.4 28.24,46.57 28.24,46.57 ; U2.4 29.04,47 ; U2.4 27.46,47 ; 86.49,15.38 C535.2 86.49,16.9 ; J3.11 50.76,6.07 ; J3.11 49.81,5.12 ; J3.11 50.76,4.17 ; J3.11 51.71,5.12 ; U19.16 15.66,17.74 v1(15.63,17.7) ; 95.58,6.6 Q8.2 ; Q8.2 95.07,7.03 ; Q8.2 95.58,7.46 ; Q8.2 96.09,7.03 ; 24.55,14.14 C27.2 23.91,13.18 ; C3.2 10.72,51.57 ; C3.2 10.72,50.56 ; C3.2 11.23,51.06 ; 34.51,19.6 C47.2 35.52,19.6 ; 3.25,45.32 J7.5 ; 109.23,28.17 C28.2 110.24,28.17 ; 105.63,49.57 C549.2 105.63,50.58 ; 28.33,42.27 C8.2 28.33,43.28 ; 5.51,37.97 C17.2 6.28,37.34 ; 30.44,24.68 R661.2 30.44,26.2 ; C6.2 18.99,45.56 ; C6.2 18.48,45.05 ; C6.2 18.48,46.07 ; C6.2 17.97,45.56 ; 32.03,36.61 R51.2 32.54,37.11 ; 94.45,3.97 R600.2 ; R600.2 94.96,4.48 ; R600.2 93.94,4.48 ; 65.02,31.55 C140.2 64.51,31.04 ; 64.54,29.46 C543.2 65.05,28.96 ; U2.5 32.04,47 ; U2.5 30.44,47 ; U2.5 31.24,46.67 ; 84.47,28.5 C143.2 82.56,28.5 ; 18.91,29.76 C26.2 ; SW9.2 7.3,9.96 ; SW9.2 7.3,8.58 ; SW9.2 8.24,9.27 ; D17.1 8.42,41.84 ; 26.33,36.04 R62.2 ; R62.2 26.84,36.55 ; R62.2 26.84,35.82 v1(27.29,35.37) ; 13.89,42.31 14.97,43.38 ; D59.2 59.46,43.5 ; D59.2 60.29,42.67 ; D59.2 58.63,42.67 ; Y1.2 23.71,33.86 ; Y1.2 23.15,33.3 ; Y1.2 22.55,34.46 ; U10.2 28.06,38.12 v1(27.93,37.99) ; v1(68.68,28.69) 68.7,28.69 68.7,28.71 68.72,28.69 U36.7 ; 45.05,10.58 C557.2 46.06,10.58 ; 20.54,22.64 C552.2 ; C552.2 20.03,23.15 ; C552.2 21.04,23.15 ; 31.2,30.7 C21.2 32.16,31.33 ; 94.45,6.51 R602.2 ; R602.2 94.96,7.02 ; R602.2 93.94,7.02 ; Q9.2 48.84,14.4 ; Q9.2 48.34,14.83 ; Q9.2 48.34,13.96 ; Q9.2 47.83,14.4 ; 26.76,7.91 C555.2 26.76,8.93 ; 11.84,30.05 R68.2 10.82,30.05 ; 52.35,5.12 J3.13 ; J3.13 53.3,6.07 ; J3.13 53.3,4.17 ; 18.85,44.67 C7.2 ; C7.2 19.87,44.67 ; C7.2 19.36,45.18 ; C7.2 19.36,44.16 ; R16.2 32.03,45.96 ; U37.20 75.6,28.69 v1(75.35,28.94) ; v1(72.48,28.97) 72.25,29.19 U37.4 ; 38.63,40.95 C10.2 38.63,41.97 ; U19.19 v1(15.69,16.24) ; 57.77,27.8 C126.2 58.36,27.8 v1(58.86,27.29) 58.36,26.78 C127.2 57.77,26.78 ; 1.21,9.27 SW9.4 ; SW9.4 2.15,9.96 ; SW9.4 2.15,8.58 ; 39.35,23.48 U26.4 ; 10.68,18.96 C536.2 ; U19.1 19.88,15.31 19.85,15.28 v1(19.85,15.21) ; 67.4,42.14 D60.2 ; D60.2 66.57,42.96 ; D60.2 68.22,42.96 ; 31.46,34.33 C18.2 ; 6.21,39.36 L2.2 6.21,38.37 ; D18.1 8.32,44.84 ; 10.48,29.82 C25.2 9.98,30.33 ; Q11.1 6.69,45.82 ; Q11.1 6.69,44.83 ; Q11.1 6.36,45.33 ; 7.02,50.98 U1.4 ; U32.4 44.98,21.87 ; C545.2 29.68,9.56 ; 39.6,17.64 U34.4 ; 35.65,19.6 C546.2 ; 110.24,33.39 R44.2 109.23,33.39 ; U8.8 v1(16.16,39.75) ; R170.1 35.14,34.2 ; U8.2 v1(18.1,42.9) ; U7.2 v1(27.8,41.16)
  TOP w0.305: U19.4 20.64,17.24 v1(20.78,17.1)
  TOP w0.381: 39.84,11.98 C128.2 ; C128.2 43.78,11.98 ; C128.2 41.81,10.96 ; C128.2 41.81,12.99 ; C548.2 v1(44.73,34.54) ; v1(24.5,17.46) 24.27,17.69 C547.2 ; C551.2 v1(12.13,12.36) ; C59.2 v1(39.84,31.69) ; C533.2 86.51,27.63 v1(86.76,27.38) ; C40.2 v1(8.7,21.37) ; v1(78.13,44.35) 78.51,43.97 R575.2 ; v1(5.38,45.54) 5.16,45.32 J7.5 ; v1(11.32,17.82) C536.2
  TOP w0.508: D60.2 v1(67.4,43.98) ; R68.2 v1(11.33,29.08) ; GND2.1 84.61,56.72 ; GND2.1 85.95,55.37 ; GND2.1 84.61,54.03 ; GND2.1 83.26,55.37 ; 1.81,28.19 J11.4 ; J11.4 3.84,28.19 ; J11.4 2.82,29.21 ; J11.4 2.82,27.18 ; J12.3 18.65,30.13 ; C553.2 v1(85.62,40.81) ; J13.4 3.84,15.62 ; J13.4 1.81,15.62 ; J13.4 2.82,16.63 ; J13.4 2.82,14.6 ; v1(21.05,22.61) 21.04,22.61 21.04,22.64 C552.2 ; C12.2 v1(13.23,38.99) ; J14.3 85.1,44.63 ; SW9.2 v1(5.97,9.27) ; 10.88,13.68 GND3.1 ; GND3.1 9.54,15.02 ; GND3.1 10.88,16.37 ; GND3.1 12.23,15.02 ; 109.66,43.7 R13.3 ; R13.3 111.69,43.7 ; R13.3 110.68,42.69 ; R13.3 110.68,44.72 ; 37.43,46.95 GND4.1 ; GND4.1 38.77,48.3 ; GND4.1 37.43,49.64 ; GND4.1 36.08,48.3 ; C555.2 v1(27.55,8.42) ; R16.2 v1(32.9,45.45) ; C11.2 v1(10.16,40.28) ; C25.2 v1(9.98,28.92) ; C5.2 v1(105.94,45.25) ; U21.5 v1(21.1,26.7) ; SW9.4 v1(3.6,9.27) ; R74.2 v1(109.74,24.29) ; v1(34.84,36.74) 34.2,36.11 C22.2 C550.2 ; 14.43,42.84 v1(13.79,43.48) ; C26.2 v1(19.42,30.49) ; L2.2 v1(5.43,38.87) ; C27.2 v1(23.91,15.28) ; R731.2 R734.2 ; C47.2 v1(35.01,20.36) ; v2(37.52,33.66) U15.2 ; C28.2 109.74,29.43 v1(109.73,29.43) C16.2 ; U11.2 v1(9.03,34.12) ; R599.2 v1(94.45,1.5) ; C546.2 v1(36.16,20.33) ; C17.2 v1(4.56,37.34) ; C8.2 v1(27.58,42.77) ; J14.5 85.1,45.9 ; R20.2 v1(21.15,44.93) ; C549.2 v1(104.93,50.08) ; v1(32.19,34.51) 31.86,34.84 C18.2 ; C535.2 v1(85.61,16.14) ; R44.2 v1(109.74,34.1) ; J12.5 18.65,31.4 ; R661.2 v1(29.57,25.44)
  TOP w0.635: C545.2 v1(29.17,8.62) ; J16.SH1 12.79,4.64 ; J16.SH1 11.87,2.58 ; J16.SH1 13.7,2.58 ; J16.2 13.69,11.8 ; J16.2 14.6,9.88 ; J16.2 12.77,9.88 ; J16.2 13.69,7.96 ; J16.3 18.89,11.8 ; J16.3 19.8,9.88 ; J16.3 18.89,7.96 ; J16.3 17.97,9.88 ; v2(31.03,9.51) C554.2 ; C21.2 30.39,31.33 v1(30.06,31.66) ; R170.1 35.52,33.69 35.55,33.66 U15.2 ; C557.2 v2(45.55,11.33) ; 21.77,2.58 J16.SH2 ; J16.SH2 22.69,4.64 ; J16.SH2 23.6,2.58 ; C24.2 v1(43.27,27.47) ; C558.2 v2(48.09,10.58) ; C556.2 v2(33.74,9.56)
  TOP w0.762: C554.2 33.69,9.51 v2(33.74,9.56)
  L2_GND_1 w0.254: J3.13 53.3,6.07 ; J3.13 54.25,5.12 ; J3.13 52.35,5.12 ; J3.13 53.3,4.17 ; J3.11 51.71,5.12 ; J3.11 50.76,4.17 ; J3.11 49.81,5.12 ; J3.11 50.76,6.07 ; 35.52,53.38 J2.7 ; J2.7 37.55,53.38 ; J2.7 36.54,52.36 ; J2.7 36.54,54.39
  L2_GND_1 w0.508: GND4.1 37.43,49.64 ; GND4.1 37.43,46.95 ; GND4.1 36.08,48.3 ; GND4.1 38.77,48.3 ; 29.86,4.23 GND1.1 ; GND1.1 31.2,5.58 ; GND1.1 31.2,2.88 ; GND1.1 32.55,4.23 ; 10.88,13.68 GND3.1 ; GND3.1 12.23,15.02 ; GND3.1 9.54,15.02 ; GND3.1 10.88,16.37 ; 110.68,42.69 R13.3 ; R13.3 110.68,44.72 ; R13.3 111.69,43.7 ; R13.3 109.66,43.7 ; J12.3 18.65,30.13 ; J13.4 3.84,15.62 ; J13.4 1.81,15.62 ; J13.4 2.82,16.63 ; J13.4 2.82,14.6 ; 2.82,27.18 J11.4 ; J11.4 1.81,28.19 ; J11.4 3.84,28.19 ; J11.4 2.82,29.21 ; GND2.1 84.61,56.72 ; GND2.1 84.61,54.03 ; GND2.1 83.26,55.37 ; GND2.1 85.95,55.37 ; J12.5 18.65,31.4 ; J14.5 85.1,45.9 ; J14.3 85.1,44.63
  L2_GND_1 w0.635: 13.69,7.96 J16.2 ; J16.2 14.6,9.88 ; J16.2 12.77,9.88 ; J16.2 13.69,11.8 ; 21.77,2.58 J16.SH2 ; J16.SH2 23.6,2.58 ; J16.SH2 22.69,4.64 ; J16.3 18.89,11.8 ; J16.3 18.89,7.96 ; J16.3 17.97,9.88 ; J16.3 19.8,9.88 ; J16.SH1 13.7,2.58 ; J16.SH1 11.87,2.58 ; J16.SH1 12.79,4.64
  L3_INT_1 w0.254: J2.7 36.54,54.39 ; J2.7 35.52,53.38 ; J2.7 37.55,53.38 ; J2.7 36.54,52.36 ; 53.3,6.07 J3.13 54.25,5.12
  L3_INT_1 w0.508: 83.26,55.37 GND2.1 ; GND2.1 84.61,56.72 ; GND2.1 85.95,55.37 ; GND2.1 84.61,54.03 ; GND3.1 10.88,16.37 ; GND3.1 9.54,15.02 ; GND3.1 12.23,15.02 ; J12.3 18.65,30.13 ; J12.5 18.65,31.4 ; J14.3 85.1,44.63 ; R13.3 110.68,44.72 ; R13.3 109.66,43.7 ; R13.3 110.68,42.69 ; R13.3 111.69,43.7 ; J14.5 85.1,45.9
  L3_INT_1 w0.635: 21.77,2.58 J16.SH2 ; J16.SH2 23.6,2.58 ; J16.SH2 22.69,4.64 ; J16.SH1 12.79,4.64 ; J16.SH1 11.87,2.58 ; J16.SH1 13.7,2.58
  L4_INT_2 w0.254: 50.76,4.17 J3.11 ; J3.11 49.81,5.12 ; J3.11 50.76,6.07 ; J3.11 51.71,5.12 ; J3.13 54.25,5.12 ; J3.13 52.35,5.12 ; J3.13 53.3,6.07 ; J3.13 53.3,4.17 ; 36.54,52.36 J2.7 ; J2.7 37.55,53.38 ; J2.7 36.54,54.39 ; J2.7 35.52,53.38
  L4_INT_2 w0.508: GND3.1 12.23,15.02 ; GND3.1 10.88,13.68 ; GND3.1 9.54,15.02 ; GND3.1 10.88,16.37 ; J14.5 85.1,45.9 ; GND2.1 85.95,55.37 ; GND2.1 83.26,55.37 ; GND2.1 84.61,54.03 ; GND2.1 84.61,56.72 ; 2.82,27.18 J11.4 ; J11.4 2.82,29.21 ; J11.4 3.84,28.19 ; J11.4 1.81,28.19 ; GND1.1 32.55,4.23 ; GND1.1 31.2,5.58 ; GND1.1 31.2,2.88 ; GND1.1 29.86,4.23 ; GND4.1 38.77,48.3 ; GND4.1 37.43,49.64 ; GND4.1 37.43,46.95 ; GND4.1 36.08,48.3 ; J13.4 3.84,15.62 ; J13.4 2.82,14.6 ; J13.4 2.82,16.63 ; J13.4 1.81,15.62 ; R13.3 110.68,44.72 ; R13.3 110.68,42.69 ; R13.3 111.69,43.7 ; R13.3 109.66,43.7 ; J12.3 18.65,30.13 ; J12.5 18.65,31.4 ; J14.3 85.1,44.63
  L4_INT_2 w0.635: J16.SH2 23.6,2.58 ; J16.SH2 21.77,2.58 ; J16.SH2 22.69,4.64 ; J16.SH1 13.7,2.58 ; J16.SH1 12.79,4.64 ; J16.SH1 11.87,2.58 ; 18.89,7.96 J16.3 ; J16.3 19.8,9.88 ; J16.3 17.97,9.88 ; J16.3 18.89,11.8 ; 12.77,9.88 J16.2 ; J16.2 13.69,11.8 ; J16.2 14.6,9.88 ; J16.2 13.69,7.96
  L5_GND_2 w0.254: 50.76,4.17 J3.11 ; J3.11 50.76,6.07 ; J3.11 51.71,5.12 ; J3.11 49.81,5.12 ; J3.13 54.25,5.12 ; J3.13 53.3,4.17 ; J3.13 52.35,5.12 ; J3.13 53.3,6.07 ; J2.7 37.55,53.38 ; J2.7 36.54,54.39 ; J2.7 35.52,53.38 ; J2.7 36.54,52.36
  L5_GND_2 w0.508: GND2.1 85.95,55.37 ; GND2.1 84.61,54.03 ; GND2.1 84.61,56.72 ; GND2.1 83.26,55.37 ; GND3.1 10.88,16.37 ; GND3.1 10.88,13.68 ; GND3.1 9.54,15.02 ; GND3.1 12.23,15.02 ; J11.4 3.84,28.19 ; J11.4 2.82,29.21 ; J11.4 1.81,28.19 ; J11.4 2.82,27.18 ; J12.5 18.65,31.4 ; 1.81,15.62 J13.4 ; J13.4 2.82,16.63 ; J13.4 3.84,15.62 ; J13.4 2.82,14.6 ; 29.86,4.23 GND1.1 ; GND1.1 31.2,5.58 ; GND1.1 32.55,4.23 ; GND1.1 31.2,2.88 ; 110.68,42.69 R13.3 ; R13.3 110.68,44.72 ; R13.3 109.66,43.7 ; R13.3 111.69,43.7 ; J14.5 85.1,45.9 ; GND4.1 38.77,48.3 ; GND4.1 36.08,48.3 ; GND4.1 37.43,49.64 ; GND4.1 37.43,46.95 ; J14.3 85.1,44.63 ; J12.3 18.65,30.13
  L5_GND_2 w0.635: 18.89,7.96 J16.3 ; J16.3 17.97,9.88 ; J16.3 19.8,9.88 ; J16.3 18.89,11.8 ; J16.SH1 12.79,4.64 ; J16.SH1 11.87,2.58 ; J16.SH1 13.7,2.58 ; J16.2 14.6,9.88 ; J16.2 13.69,7.96 ; J16.2 12.77,9.88 ; J16.2 13.69,11.8 ; J16.SH2 22.69,4.64 ; J16.SH2 21.77,2.58 ; J16.SH2 23.6,2.58
  BOTTOM w0.254: 36.54,52.36 J2.7 ; J2.7 36.54,54.39 ; J2.7 35.52,53.38 ; J2.7 37.55,53.38 ; 49.81,5.12 J3.11 ; J3.11 50.76,6.07 ; J3.11 50.76,4.17 ; J3.13 53.3,6.07 ; J3.13 54.25,5.12 ; J3.13 52.35,5.12 ; J3.13 53.3,4.17
  BOTTOM w0.508: J12.3 18.65,30.13 ; GND4.1 37.43,49.64 ; GND4.1 36.08,48.3 ; GND4.1 38.77,48.3 ; J12.5 18.65,31.4 ; 2.82,14.6 J13.4 ; J13.4 1.81,15.62 ; J13.4 3.84,15.62 ; J13.4 2.82,16.63 ; GND1.1 31.2,5.58 ; GND1.1 31.2,2.88 ; GND1.1 29.86,4.23 ; GND1.1 32.55,4.23 ; 2.82,27.18 J11.4 ; J11.4 3.84,28.19 ; J11.4 1.81,28.19 ; J11.4 2.82,29.21 ; 10.88,13.68 GND3.1 ; GND3.1 9.54,15.02 ; GND3.1 10.88,16.37 ; J14.5 85.1,45.9 ; J14.3 85.1,44.63
  BOTTOM w0.635: 21.77,2.58 J16.SH2 ; J16.SH2 22.69,4.64 ; J16.SH2 23.6,2.58 ; 13.69,7.96 J16.2 ; J16.2 12.77,9.88 ; J16.2 14.6,9.88 ; J16.2 13.69,11.8 ; J16.3 19.8,9.88 ; J16.3 18.89,7.96 ; J16.3 17.97,9.88 ; J16.3 18.89,11.8 ; J16.SH1 12.79,4.64 ; J16.SH1 11.87,2.58 ; J16.SH1 13.7,2.58
  vias: v1(1.29,8.13) v1(1.42,37.97) v1(1.42,32) v1(1.42,26.29) v1(1.42,24.64) v1(1.42,21.84) v1(1.42,19.43) v1(1.42,17.02) v1(1.42,14.48) v1(1.42,12.57) v1(1.55,29.46) v1(1.67,50.8) v1(1.8,5.97) v1(1.89,13.55) v1(2.37,37.81) v1(2.48,25.79) v1(2.82,53.47) v1(2.97,4.09) v1(3.07,52.7) v1(3.33,54.36) v1(4.24,25.65) v1(4.6,2.67) v1(4.72,55.63) v1(6.06,21.63) v1(6.88,26.67) v1(6.88,1.65) v1(8.41,55.75) v1(9.29,57.15) v1(9.68,1.27) v1(10.72,52.43) v1(10.82,57.15) v1(11.38,55.42) v1(11.71,11.18) v1(11.71,53.25) v1(12.18,5.78) v1(13.99,13.34) v1(15.01,1.27) v1(15.64,10.92) v1(15.64,9.91) v1(15.64,8.89) v1(15.64,7.62) v1(16.15,57.28) v1(16.28,13.34) v1(16.66,10.92) v1(16.66,9.91) v1(16.79,8.89) v1(16.79,7.62) v1(16.79,1.27) v1(18.05,39.02) v1(18.24,20.05) v1(18.23,15.84) v1(18.57,57.28) v1(18.69,1.27) v1(18.73,39.71) v1(18.83,38.21) v1(19.27,45.56) v1(19.52,40.53) v1(19.53,38.91) v1(19.71,54.86) v1(20.2,41.2) v1(20.34,57.28) v1(20.33,39.71) v1(21.01,40.39) v1(20.99,32.73) v1(21.6,31.58) v1(22.01,57.19) v1(22.38,47.24) v1(22.58,55.42) v1(23.39,53.47) v1(23.9,57.28) v1(24.05,25.46) v1(24.4,3.09) v1(24.52,1.66) v1(25.55,57.28) v1(25.93,32.38) v1(26.33,56.55) v1(26.57,50.16) v1(27.84,57.28) v1(29.68,1.77) v1(30.38,57.28) v1(31.77,56.52) v1(32.69,42.47) v1(32.77,37.11) v1(38.63,40.69) v1(46.48,46.38) v1(46.44,14.39) v1(46.63,47.88) v1(49.68,8.64) v1(49.81,47.88) v1(50.06,56.77) v1(51.59,56.9) v1(52.22,42.55) v1(52.87,56.43) v1(53.98,51.72) v1(57.17,30.48) v1(57.47,43.95) v1(58.33,48.91) v1(58.57,51.31) v1(58.95,30.61) v1(58.95,29.72) v1(58.92,12.53) v1(59.63,43.7) v1(61.79,43.7) v1(61.75,36.2) v1(63.24,32.2) v1(63.3,31.17) v1(63.9,38.86) v1(64.36,29.6) v1(65.3,36.58) v1(66.32,50.55) v1(67.09,28.68) v1(67.11,25.78) v1(67.79,36.32) v1(69.06,43.79) v1(69.18,36.36) v1(70,22.05) v1(70.18,43.76) v1(72.03,46.1) v1(72.28,36.01) v1(72.45,30.52) v1(72.45,27.42) v1(74.03,30.49) v1(74.03,28.94) v1(74.03,27.39) v1(75.58,30.47) v1(75.53,27.42) v1(75.72,56.9) v1(76.48,50.67) v1(77.37,56.9) v1(78.08,13.36) v1(78.24,56.48) v1(78.78,15.55) v1(80.03,46.89) v1(80.89,26.96) v1(82.32,56.9) v1(82.74,15.15) v1(83.02,12.67) v1(83.17,17.54) v1(84.73,36.83) v1(85.36,6.95) v1(85.37,2.79) v1(85.62,1.27) v1(86.51,37.85) v1(87.15,56.77) v1(87.32,4.09) v1(89.94,30.35) v1(90.19,56.77) v1(90.45,26.8) v1(91.97,1.27) v1(93.66,7.02) v1(94.3,30.01) v1(94.77,56.64) v1(96.28,4.2) v1(96.67,55.37) v1(97.43,1.4) v1(99.46,56.77) v1(102.13,56.64) v1(104.29,56.77) v1(104.93,2.54) v1(106.06,7.07) v1(106.45,56.64) v1(106.69,38.85) v1(106.62,14.67) v1(108.74,56.01) v1(108.99,1.91) v1(109.05,5.42) v1(110.51,3.05) v1(111.4,53.59) v1(112.16,4.83) v1(113.18,51.69) v1(113.31,6.48) v1(113.69,49.15) v1(113.69,46.23) v1(113.69,23.49) v1(113.82,43.05) v1(113.82,40) v1(113.82,35.05) v1(113.82,29.72) v1(113.82,12.07) v2(42.06,9.75) v2(43.27,10.5) v2(43.37,13.63) v2(44.11,11.98)
